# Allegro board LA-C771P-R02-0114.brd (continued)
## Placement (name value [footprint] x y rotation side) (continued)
RX6  -  [R_0402]  51.14 93.02 90 bottom
RX7  -  [R0402_0OHM]  48.93 92.08 0 bottom
RX8  -  [R_0402]  50.2 93.99 180 bottom
RX9  -  [R0805_0OHM]  73.36 98.61 270 bottom
RX10  -  [R0603_0OHM]  54.82 90.15 90 bottom
RX11  -  [R_0402]  50.83 83.57 0 bottom
RX12  -  [R0402_0OHM]  50.12 95.89 0 bottom
RX13  -  [R0402_0OHM]  50.12 96.78 0 bottom
RY1  -  [R_0402]  18.96 84.2 180 top
RY2  -  [R_0402]  13.87 94.75 90 top
RY3  -  [R_0402]  18.96 85.22 180 top
RY4  -  [R_0402]  18.96 81.03 180 top
RY5  -  [R_0402]  18.96 80.15 180 top
RY6  -  [R_0402]  18.96 82.94 180 top
RY7  -  [R_0402]  18.96 86.13 180 top
RY8  -  [R_0402]  18.96 82.05 180 top
RY9  -  [R_0402]  18.97 87.15 180 top
RY10  -  [R_0402]  15.52 93.78 0 top
RY11  -  [R_0402]  21.03 87.09 180 bottom
RY12  -  [R_0402]  18.7 86.24 90 bottom
RY13  -  [R_0402]  21.03 86.2 180 bottom
RY14  -  [R_0402]  21.2 82.01 180 bottom
RY15  -  [R_0402]  18.83 83.06 270 bottom
RY16  -  [R_0402]  21.2 82.9 180 bottom
RY17  -  [R_0402]  20.99 85.15 180 bottom
RY18  -  [R_0402]  18.7 84.46 90 bottom
RY19  -  [R_0402]  20.99 84.27 180 bottom
RY20  -  [R_0402]  21.17 80.11 180 bottom
RY21  -  [R_0402]  18.83 81.29 270 bottom
RY22  -  [R_0402]  21.17 81.01 180 bottom
SW3  -  [SW_TJG-533-V-T-R_6P]  108.35 5.6 90 top
SW4  -  [SW_TJG-533-V-T-R_6P]  180.1 5.6 90 top
SW5  -  [SW_NTC325-EA1J-A160C_3P]  4.3 9.89 270 top
T1  -  [TPC12]  94.57 75.22 180 bottom
T2  -  [TPC12]  95.85 75.45 180 bottom
T3  -  [TPC12]  116.69 83.85 0 top
T4  -  [TPC12]  122.84 78.45 180 bottom
T5  -  [TPC12]  123.63 81.42 180 bottom
T6  -  [TPC12]  122.72 82.5 315 top
T7  -  [TPC12]  124.63 88 180 bottom
T8  -  [TPC12]  101.61 78.79 45 top
T9  -  [TPC12]  93.68 80.91 180 bottom
T10  -  [TPC12]  101.68 80.07 0 top
T11  -  [TPC12]  102.93 80.68 0 top
T12  -  [TPC12]  101.84 81.44 0 top
T13  -  [TPC12]  102.27 82.68 0 top
T14  -  [TPC12]  119.28 83.83 315 top
T15  -  [TPC12]  118.73 81.77 315 top
T16  -  [TPC12]  123.81 76.2 180 bottom
T17  -  [TPC12]  122.95 77.13 180 bottom
T18  -  [TPC12]  123.58 74.92 180 bottom
T19  -  [TPC12]  123.63 73.52 180 bottom
T20  -  [TPC12]  106.2 79.74 45 top
T21  -  [TPC12]  110.05 76.67 45 top
T22  -  [TPC12]  222.82 108.92 0 top
TL1  -  [MHPC_NS681612A_16P]  26.84 70.09 270 bottom
TPL1  -  [TPC12]  39.73 64.11 180 bottom
TPL2  -  [TPC12]  37.98 65.06 180 bottom
UA1  -  [ALC233-VB2-CG_MQFN48_6X6]  26.97 27.53 180 top
UB1  -  [NPCE388NA0DX_LQFP128_14X14]  78.13 27.8 270 top
UC4  -  [VALLEYVIEW-M_FCBGA_1170P-T]  97.84 90.26 90 bottom
UC5  -  [SN74LVC1G07DCKR_SC70-5]  56.65 80.15 270 bottom
UC6  -  [SN74LVC1G07DCKR_SC70-5]  61.96 80.26 270 bottom
UC7  -  [SN74LVC1G07DCKR_SC70-5]  83.27 75.11 90 top
UC8  -  [TC7SH08FUF_SSOP5]  78.66 80.92 90 top
UC9  -  [SN74LVC1G07DCKR_SC70-5]  95.41 95 270 bottom
UC10  -  [W25Q64DWSSIG_SO8]  54.83 46.05 180 top
UL1  -  [RTL8111GS-CG_QFN32_4X4]  33.63 67.35 90 bottom
UQ1  -  [TPS22966DPUR_SON14_2X3]  189.53 24.2 90 top
UQ2  -  [TPS22966DPUR_SON14_2X3]  51.18 68.68 270 top
UQ3  -  [AO4304L_SO8]  156.71 53.14 270 top
UR1  -  [RTS5220-GRT_QFN24_4X4]  48.68 15.53 270 top
US1  -  [SY6288D20AAC_SOT23-5]  18.38 39.3 180 bottom
US2  -  [FE1P1S-BQFN24B_WQFN24_4X4]  197.75 57.57 180 top
US3  -  [SY6288D20AAC_SOT23-5]  186.98 53.6 270 top
UW1  -  [Z32H320TC-LPC-T28-233_TSSOP28]  98.54 20.3 90 top
UW2  -  [MAX9180EXTLFT_SC70-6]  99.04 15.59 90 top
UX1  -  [SY6288C20AAC_SOT23-5]  72.07 86.41 270 top
UY1  -  [AP2330W-7_SC59-3]  16.92 89.41 180 top
YC1  -  [Y_7V25000014_4P]  111.07 95.72 180 bottom
YC2  -  [Y_Q13FC135000040_2P]  90.65 92.26 270 bottom
YL1  -  [Y_X3G025000DC1H_4P]  37.65 61.4 270 bottom
YS1  -  [Y_CRG3201212_4P]  202.09 60.46 180 top

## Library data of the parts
C1 C5 C6 C9-C11 CB1 CB8 CB13 CB14 CC1 CC6-CC11 CC15 CC17 CC22 CC23 CC30 CC79 CC85 CC89 CC90 CC92 CD1 CD3 CD8-CD15 CD19 CO12 CQ3-CQ5 CQ7 CQ11-CQ13 CQ15 CQ19 CQ20 CS1-CS3 CS7 CS8 CS13 CX3-CX8 CX11 CX13 CY1-CY12 = C_0402: tolerance: .1U_0402_16V7K
C2 C12 CO13 CO14 = C_0603: tolerance: 0.1U_0603_6.3V6M
C3 C4 CB7 CB10 CC2-CC5 CC14 CC16 CC21 PC101 PC102 PC713 PC757 = C_0402: tolerance: 100P_0402_50V8J
CA1 CA3 CA5-CA7 CM1 = C_0402: tolerance: 0.1U_0402_16VK7
CA2 CA8 CA9 CA15 CA20 CA22-CA24 CC24 CC25 CC29 CC31 CC32 CC41-CC53 CC56-CC71 CC74 CC76-CC78 CC80-CC84 CC87 CC88 CC91 CC93 CD17 CD18 CL1 CL6 CO11 CQ1 CQ8 CQ9 CQ16 CR10 CX2 CX10 PC601 PC706-PC708 PC733 PC738 = C_0402: tolerance: 1U_0402_6.3V6K
CA4 CA18 CB11 CL9 CL10 CQ17 CQ18 CR1 CR3 CR5 CR11 CX1 PC602 = C_0603: tolerance: 4.7U_0603_6.3V6K
CA10 = C_0402: tolerance: 22P_0402_50V8J
CA11 CA14 CA17 CA19 CS5 CS6 PC714 PC756 = C_0402: tolerance: 470P_0402_50V7K
CA12 CA13 CA16 CA21 CA25 CC33-CC36 PC781 PC784 = C_0402: tolerance: 2.2U_0402_6.3V6M
CA28 CA29 CB2 CB5 CB6 PC100 PC103 PC104 PC210 PC705 = C_0402: tolerance: 1000P_0402_50V7K
CA30 CA32 = C_0402: tolerance: 0.1U_0402_16V4Z
CA31 CL2-CL5 CL7 CL8 CL11 CL12 CR2 CR4 CR6-CR8 CR12 PC501 PC603 PC710-PC712 PC750 = C_0402: tolerance: 0.1U_0402_16V7K
CB3 CB4 CW1-CW4 = C_0201: tolerance: 0.1U_0201_10V6K
CB12 PC744 = C_0402: tolerance: 47P_0402_50V8J
CC12 CC13 = C_0402: tolerance: 10P_0402_25V8J
CC18 CC19 = C_0402: tolerance: 15P_0402_50V8J
CC20 CC94 CC95 CD2 = C_0402: tolerance: 100P_0402_25V8K
CC26-CC28 CL13 CL16 = C_0402: tolerance: 10P_0402_50V8J
CC37-CC40 CC72 CC73 CC75 CD4-CD7 CD16 CO9 CO10 CS9 CX12 PC406 PC407 PC702-PC704 PC715 PC718 PC723 PC766 PC770 PC774 PC777 PC779 = C_0603: tolerance: 10U_0603_6.3V6M
CC54 = C_0402: tolerance: 0.47U_0402_6.3V6K
CC55 CC86 CL15 CO1-CO8 CS11 CS12 = C_0402: tolerance: 0.01U_0402_16V7K
CL14 = C_0603: tolerance: 10P_0603_50V
CLRP1 CLRP2 J1 J2 = SHORTPADS: User Part Number: PART#; tolerance: SHORT PADS
CQ2 CQ6 CQ10 CQ14 PC724 PC752 PC762 = C_0402: tolerance: 330P_0402_50V7K
CR9 = C_0402: tolerance: 5.6P 50V D NPO 0402
CS4 CS14 = C_MP6VLPS220MC4R2: tolerance: 220U_6.3V_M
CS10 PC311 PC320 PC325 = C_0603: tolerance: 4.7U_0603_6.3V6M
CX9 = C_0805: tolerance: 4.7U_0805_25V6-K
CX14 CX15 = C_0402: tolerance: 33P_0402_50V8K
D1 = YSLC05CH_SOT23-3
D2 = PSOT24C_SOT23-3: tolerance: L30ESD24VC3-2
D3 = PSOT24C_SOT23-3: tolerance: SCA00002900
D4 DA3-DA5 = L03ESDL5V0CC3-2_SOT23-3
DC1 = RB751V40_SC76-2
DL1 = BS4200N-C-LV_SMB-F2
DL2 DS2 DS3 = AZC099-04SPR7G_SOT23-6: tolerance: AZC099-04S.R7G_SOT23-6
DS1 DY1-DY3 = L05ESDL5V0NA-4_SLP2510P8-10-9
FD1-FD4 = FIDUCIAL_C40M80: tolerance: CF
H1-H5 H7 H8 H13 H14 = H_3P0: tolerance: HOLEA
H6 = H_3P1X3P6: tolerance: HOLEA
H9-H12 = H_3P8: tolerance: HOLEA
JBATT1 = SUYIN_125022HB008M200ZL_8P-T: tolerance: SUYIN_125022HB008M200ZL
JDCIN1 = ACES_50299-00501-003_5P: tolerance: ACES_88299-0510
JDIMM1 = LCN_DAN06-K4406-0102_204P: tolerance: LCN_DAN06-K4406-0102
JEDP1 = ACES_87242-3001-09_30P: tolerance: ACES_87242-3001-09
JHDD1 = SDAN_603015-022041_22P-T: tolerance: SDAN_603015-022041
JHDMI1 = LOTES_AHDM0006-P004A_19P: tolerance: LOTES_AHDM0006-P004A
JHP1 = SANTA_311108-1_7P: tolerance: SANTA_311108-1
JKB1 JKB2 = ACES_88514-3001_30P: tolerance: ACES_88514-3001
JLAN1 = SANTA_130452-S_8P: tolerance: SANTA_130452-S
JODD1 = SANTA_201304-1_13P: tolerance: SANTA_201304-1
JP1 = ACES_85205-0400_4P: tolerance: ACES_85205-0400
JPWRB1 JSB1 JTP1 = ACES_88058-060N_6P: tolerance: ACES_88058-060N
JRTC1 = LOTES_AAA-BAT-054-K01_2P: tolerance: LOTES_AAA-BAT-054-K01
JSD1 = FOX_WK21921-R93-9H_11P: tolerance: FOX_WK21921-R93-9H
JSPK1 = E-T_3806K-F02N-03R_2P: tolerance: E&T_3806K-F02N-03R
JUSB1 = SINGA_2UB4039-200011F_9P: tolerance: SINGA_2UB4039-200011F
JUSB2 = SDAN_608050-004041_4P: tolerance: SDAN_608050-004041
JWLAN1 = BELLW_80019-1021_52P: tolerance: BELLW_80019-1021
L1 L2 = TDK_MPZ2012S101AT000_2P: tolerance: MPZ2012S101AT000_2P
L3 L4 = L_FBM-11-160808_2P: tolerance: FBM-11-160808-601-T_0603
LA1 LA2 = CHENG_MBK1608121YZF_2P: tolerance: FCM1608CF-121T03 0603
LED1 LED3 LED4 = LED_19-217-T1D-DP1Q2QY-3T_2P: tolerance: 19-217-T1D-DP1Q2QY-3T_WHITE
LED2 = LED_19-213A-T1D-CP2Q2HY-3T_2P: tolerance: 19-217/S2C-FM2P1VY/3T 0603 ORANGE
LR1 = MURAT_BLM18PG300SN1D_2P: tolerance: PBY160808T-301Y-N_0603
LS1 LS2 = INPAQ_HCM1012GH900BP_4P: tolerance: PANASONIC EXC24CH900U
LS3 LS4 LX1 LY1-LY4 = INPAQ_HCM1012GH900BP_4P: tolerance: HCM1012GH900BP_4P
MIC1 = MIC_WM-64PCY_2P: tolerance: KECG2242PFL-B4
PC105 PC209 PC302 PC604 = C_0402: tolerance: 0.01U_0402_25V7K
PC200 = C_0603: tolerance: 1000P_0603_50V7
PC201 = C_0603: tolerance: 0.022U_0603_25V7K
PC202 PC214 = C_0603: tolerance: 0.047U_0603_25V7M
PC203 PC503 = C_0402: tolerance: 68P_0402_50V8J
PC204 PC212 PC303 PC316 PC402 PC720 = C_0402: tolerance: 2200P_0402_50V7K
PC205 PC206 PC218 PC220 PC305 PC306 PC314 PC315 PC403 PC404 PC721 PC722 PC739 PC741 = C_0805: tolerance: 10U_0805_25V6K
PC207 = C_0603: tolerance: 0.1U_0603_25V7M
PC208 PC217 PC221-PC223 PC301 PC319 PC401 PC725 PC740 PC751 = C_0402: tolerance: 0.1U_0402_25V6
PC211 = C_0603: tolerance: 1U_0603_25V6K
PC213 = C_0805: tolerance: 2.2U_0805_25V6K
PC215 PC216 = C_0603: tolerance: 100P_0603_50V8
PC219 PC312 PC326 = C_0603: tolerance: 680P_0603_50V7K
PC304 PC318 PC405 = C_0603: tolerance: 0.1U_0603_25V7K
PC307-PC310 PC321-PC324 PC409-PC414 PC502 PC504-PC507 PC605 PC732 PC734-PC736 PC742 PC743 PC745-PC749 PC764 PC765 PC767-PC769 PC771 PC773 PC775 PC778 PC780 PC783 = C_0603: tolerance: 22U_0603_6.3V6M
PC313 = C_0402: tolerance: 4.7U_0402_6.3V6M
PC317 PC716 PC761 = C_0402: tolerance: 6800P_0402_25V7K
PC327 = C_0402: tolerance: 1000P_0402_25V8J
PC408 PC416 = C_0402: tolerance: 1U_0402_10V6K
PC415 = C_0402: tolerance: 0.033U_0402_16V7K
PC417 PC508 PC731 PC755 = C_0402: tolerance: 680P_0402_50V7K
PC418 PC419 = C_0402: tolerance: 0.1U_0402_10V7K
PC701 = C_6P3X4P5: tolerance: 33U_25V_NC_6.3X4.5
PC709 PC763 = C_0402: tolerance: 0.01UF_0402_25V7K
PC717 = C_0402: tolerance: 10U_0402_6.3V6M
PC719 PC760 = C_0402: tolerance: 1000P_0402_50V8-J
PC726 PC759 = C_0402: tolerance: 0.1U_0402_25V6K
PC727 PC758 = C_0402: tolerance: 0.047U_0402_25V7K
PC772 PC776 = C_0603: tolerance: 4.7U_0603_10V6K
PC782 PC785-PC787 = C_D2: tolerance: 330U_D2_2V_Y
PD1 PD100 = RB715F_SOT323-3: tolerance: S SCH DIO BAS40CW SOT-323
PF100 PF101 = F_1206: tolerance: 7A_24VDC_429007.WRML
PH100 = R_0402: tolerance: 100K_0402_1%_TSM0B104F4251RZ
PH701 PH702 = R_0402: tolerance: 10K_0402_1%_B25/50 3370K
PH703 PH704 = R_0402: tolerance: 470K_0402_5%_B25/50 4700K
PJ1-PJ4 = JUMP_43X118: tolerance: JUMP
PJ5 PJ6 = JUMP_43X79: tolerance: JUMP
PJ301 PJ302 PJ401 PJ402 = JUMP_43X118
PJ403 = JUMP_43X39
PJ501 PJ502 PJ601 PJ602 = JUMP_43X79
PL100-PL103 PL301 PL303 PL401 PL701 = TAI-T_HCB2012KF-121T50_2P: tolerance: HCB2012KF-121T50_0805
PL200 = TAIYO_NRS4018T1R0NDGJ_2P: tolerance: 1UH_NRS4018T1R0NDGJ_3.2A_30%
PL201 = CYNTE_PCMB063T-4R7MS_2P: tolerance: 4.7UH_PCMB063T-4R7MS_5.5A_20%
PL302 PL304 = CYNTE_PCMC063T-1R5MN_2P: tolerance: 1.5UH_PCMC063T-1R5MN_9A_20%
PL402 = L_7X7X3_M_2P: tolerance: 1UH_11A_20%_7X7X3_M
PL403 = L_4X4X2_F_2P: tolerance: 1UH_2.8A_30%_4X4X2_F
PL702 PL703 = CYNTE_PDME064T-R36MS1R405_4P: tolerance: 0.36UH_PDME064T-R36MS_24A_20%
PQ200 = 2N7002KW_SOT323-3
PQ201 = MDU1512RH_POWERDFN56-8-5
PQ202 = AON7506_DFN33-8-5
PQ203 = AO4466L_SO8: tolerance: AO4406L_SO8
PQ204 PQ205 = SIS412DN-T1-GE3_POWERPAK8-5: tolerance: AON7408L_DFN8-5
PQ401 = AON7408L_DFN8-5
PQ402 = AON7406L_DFN8-5
PQ701 PQ702 = AON7934_DFN3X3A8-10: tolerance: AON7934_DFN3X3A-8-10
PR102 PR104 RC71-RC73 = R_0402: tolerance: 100_0402_1%
PR105 PR107 RA16 = R_0402: tolerance: 200K_0402_1%
PR109 RA10 RA22 RA23 RA31 RB12 RB18 RB20 RB21 RB27 RB31 RB32 RC14 RC15 RC17 RC21 RC22 RC27-RC29 RC32-RC36 RC43 RC58 RC59 RC61 RC63 RC81 RL4 RM18-RM20 RQ8 RQ9 RR8 RS10 RS14 RW8 RX3 RY2 = R_0402: tolerance: 10K_0402_5%
PR110 = R_0402: tolerance: 16.5K_0402_1%
PR111 PR409 PR605 = R_0402: tolerance: 10K_0402_1%
PR112 = R_0402: tolerance: 30K_0402_1%
PR113 PR225 PR228 RC1 RC2 RX8 = R_0402: tolerance: 100K_0402_1%
PR115 PR116 = R_0603: tolerance: 1K_0603_5%
PR122 PR218 PR219 PR224 PR307 PR410 PR411 PR501 PR717 PR718 PR722 R1 R15 RA8 RA9 RA12 RA21 RA24 RA26 RA28 RB7 RB22 RB24 RB26 RC10 RC13 RC23 RC48 RC70 RC74 RC75 RC80 RD5 RD6 RL5 RL7 RM4-RM6 RR5-RR7 RS6-RS9 RX1 RX7 RX12 RX13 = R0402_0OHM: tolerance: 0_0402_5%
PR123 R2 R12 RB1 RB3 RB6 RB11 RB13 RB16 RB17 RB23 RB25 RB29 RB30 RC8 RC12 RC54 RC62 RC78 RC79 RC83 RC84 RM2 RM3 RM11 RM12 RM14-RM17 RM21 RO5 RS1-RS5 RS16-RS20 RW1 RW3 RW4 RW6 RW9 RX6 = R_0402: tolerance: 0_0402_5%
PR200 PR308 = R_0402: tolerance: 1M_0402_1%
PR201 = R_0402: tolerance: 3M_0402_5%
PR202 PR221 = R_1206_4P-D: tolerance: 0.01_1206_1%
PR209 PR211 PR212 RC30 = R_0402: tolerance: 4.02K_0402_1%
PR210 = R_0603: tolerance: 4.7_0603_1%
PR213 PR226 PR227 = R_0402: tolerance: 10_0402_1%
PR214 = R_1206: tolerance: 10_1206_5%
PR215 = R_0402: tolerance: 422K_0402_1%
PR216 = R_0402: tolerance: 66.5K_0402_1%
PR217 PR220 PR708 PR728 RB2 RS15 = R_0603: tolerance: 0_0603_5%
PR222 = R_0402: tolerance: 316K_0402_1%
PR223 PR305 PR311 PR403 PR713 PR731 = R_1206: tolerance: 4.7_1206_5%
PR229 = R_0402: tolerance: 120K_0402_1%
PR301 = R_0402: tolerance: 499K_0402_1%
PR302 PR309 RA30 RL2 = R_0402: tolerance: 1K_0402_5%
PR303 = R_0402: tolerance: 150K_0402_1%
PR304 PR310 PR401 PR709 PR730 = R_0603: tolerance: 2.2_0603_5%
PR306 RA6 RA7 RA27 RC9 RC26 RW5 RW7 = R_0402: tolerance: 2.2K_0402_5%
PR312 = R_0402: tolerance: 560K_0402_5%
PR313 = R_0402: tolerance: 105K_0402_1%
PR314 PR406 PR502 PR602 R3 R16 RA14 RA15 RC37 RM13 RQ1 RQ5 RS12 RS13 RX2 RX4 RX5 RY10 = R_0402: tolerance: 100K_0402_5%
PR402 = R_0402: tolerance: 27K_0402_1%
PR404 PR405 = R_0603: tolerance: 5.1_0603_5%
PR407 = R_0402: tolerance: 8.06K_0402_1%
PR408 = R_0402: tolerance: 470K_0402_1%
PR503 RC24 = R_0402: tolerance: 1M_0402_5%
PR504 = R_0603: tolerance: 4.7_0603_5%
PR505 = R_0402: tolerance: 15K_0402_1%
PR506 RC47 RC49 = R_0402: tolerance: 20K_0402_1%
PR601 = R_0402: tolerance: 100_0402_5%
PR603 = R_0402: tolerance: 12.7K_0402_1%
PR604 RB5 RB10 RQ4 = R_0402: tolerance: 47K_0402_5%
PR701 PR724 PR736 = R_0402: tolerance: 499_0402_1%
PR702 PR741 = R_0402: tolerance: 137K_0402_1%
PR703 = R_0402: tolerance: 2.05K_0402_1%
PR704 PR705 PR733 PR737 = R_0402: tolerance: 2K_0402_1%
PR706 = R_0402: tolerance: 316_0402_1%
PR707 = R_0402: tolerance: 21K_0402_1%
PR710 PR734 = R_0402: tolerance: 2.61K_0402_1%
PR711 PR739 = R_0402: tolerance: 11K_0402_1%
PR712 PR729 = R_0402: tolerance: 1.91K_0402_1%
PR714 PR735 = R_0603: tolerance: 3.65K_0603_1%
PR715 PR727 = R_0402: tolerance: 27.4K_0402_1%
PR716 PR723 = R_0402: tolerance: 3.83K_0402_1%
PR719 = R_0402: tolerance: 1_0402_5%
PR720 RC40 = R_0402: tolerance: 20_0402_1%
PR721 RC41 = R_0402: tolerance: 16.9_0402_1%
PR725 PR726 RC39 = R_0402: tolerance: 73.2_0402_1%
PR732 = R_0402: tolerance: 64.9K_0402_1%
PR738 = R_0402: tolerance: 280_0402_1%
PR740 = R_0402: tolerance: 1.78K_0402_1%
PU1 = BQ24780RUYR_WQFN28_4X4
PU301 = SYX196BQNC_QFN10_3X3
PU302 = SYX196CQNC_QFN10_3X3: tolerance: SYX196C1QNC_QFN10_3X3
PU303 = RT8207PGQW_WQFN20_3X3
PU501 = SY8003DFC_DFN8_2X2: tolerance: SY8003ADFC_DFN8_2X2
PU601 = APL5930KAI-TRG_SO8: tolerance: AP7175SP-13 SO-8EP
PU602 = ISL95833HRTZ-T_TQFN32_4X4
Q2-Q5 QB1 QX1 = 2N7002K_SOT23-3
QC1-QC5 QY2 QY3 = MESS138W-G_SOT323-3: tolerance: BSS138W-7-F_SOT323-3
QM1 = AO5804EL_SC89-6: tolerance: DMN2400UV-7 2N SOT-563-6
QX2 = PMV65XP_SOT23-3: tolerance: DMG2301U-7 1P SOT23-3
QY1 = DMN66D0LDW-7_SOT363-6
R6 = R_0402: tolerance: 300_0402_5%
R7 = R_0402: tolerance: 620_0402_5%
R13 R14 = R_0402: tolerance: 330_0402_5%
RA1-RA5 RB4 RC76 RC77 RL1 RX10 = R0603_0OHM: tolerance: 0_0603_5%
RA11 RA13 RC53 RR4 RW2 = R_0402: tolerance: 33_0402_5%
RA17 RA18 = R_0603: tolerance: TAI-TECH FCM1608CF-121T03 0603
RA19 RA20 = R_0402: tolerance: 47_0402_5%
RA25 RA29 RB8 RB9 RB14 RB15 RC25 = R_0402: tolerance: 4.7K_0402_5%
RA32 = R_0402: tolerance: 0_0402_1%
RC3 = R_0402: tolerance: 23.2_0402_1%
RC4 = R_0402: tolerance: 29.4_0402_1%
RC5 = R_0402: tolerance: 162_0402_1%
RC6 RC7 RD1-RD4 = R_0402: tolerance: 4.7K_0402_1%
RC11 RC16 RC18 = R_0402: tolerance: 402_0402_1%
RC19 RC44 RC65 = R_0402: tolerance: 49.9_0402_1%
RC20 = R_0402: tolerance: 69.8_0402_1%
RC31 = R_0402: tolerance: 47.5_0402_1%
RC38 RC46 = R_0402: tolerance: 51_0402_5%
RC42 = R_0402: tolerance: 10M_0402_5%
RC45 = R_0402: tolerance: 200_0402_5%
RC50-RC52 = R_0402: tolerance: 3.3K_0402_5%
RC55 = R_0402: tolerance: 1.24K_0402_1%
RC56 RC57 = R_0402: tolerance: 1K_0402_1%
RC60 RC64 = R_0402: tolerance: 45.3_0402_1%
RC66 RC67 = R_0402: tolerance: 22_0402_5%
RC68 RC82 = R_0402: tolerance: 8.2K_0402_5%
RC69 = R_0402: tolerance: BLM15AX601SN1D
RL3 = R_0402: tolerance: 15K_0402_5%
RL6 = R_0402: tolerance: 2.49K_0402_1%
RL8 = R_0805: tolerance: 75_0805_5%
RM1 RO1 RO2 RO4 RX9 = R0805_0OHM: tolerance: 0_0805_5%
RPB1 RPY1 = RP_0804_8P4R: tolerance: 2.2K_0804_8P4R_5%
RPC1 RPC9 = RP_0804_8P4R: tolerance: 4.7K_0804_8P4R_5%
RPC2 = RP_0804_8P4R: tolerance: 100K_0804_8P4R_5%
RPC3 RPC5 = RP_0804_8P4R: tolerance: 10K_0804_8P4R_5%
RPC4 = RP_0804_8P4R: tolerance: 33_0804_8P4R_5%
RPC6 = RP_0804_8P4R: tolerance: 51_0804_8P4R_5%
RPC7 RPC8 = RP_0804_8P4R: tolerance: 22_0804_8P4R_5%
RQ2 = R_0402: tolerance: 120K_0402_5%
RQ3 = R_0402: tolerance: 82K_0402_5%
RQ6 = R_0603: tolerance: 22_0603_5%
RQ7 = R_0603: tolerance: 470_0603_5%
RR1 = R_0402: tolerance: 6.2K_0402_1%
RR2 RR3 = R0402_0OHM: tolerance: 0_0402_5%; signal model: R_0402_22_0402_5%
RS11 = R_0402: tolerance: 2.7K_0402_1%
RX11 = R_0402: tolerance: 150K_0402_5%
RY1 RY3-RY9 = R_0402: tolerance: 619_0402_1%
RY11 RY13 RY14 RY16 RY17 RY19 RY20 RY22 = R_0402: tolerance: 8.2_0402_1%
RY12 RY15 RY18 RY21 = R_0402: tolerance: 150_0402_5%
SW3 SW4 = SW_TJG-533-V-T-R_6P: tolerance: SMT1-05_4P
SW5 = SW_NTC325-EA1J-A160C_3P: tolerance: NTC325-EA1J-A160C_3P
T1-T22 = TPC12: tolerance: PAD
TL1 = MHPC_NS681612A_16P: tolerance: 300UH_NS681612A
TPL1 TPL2 = TPC12: tolerance: PAD~D
UA1 = ALC233-VB2-CG_MQFN48_6X6
UB1 = NPCE388NA0DX_LQFP128_14X14
UC4 = VALLEYVIEW-M_FCBGA_1170P-T: tolerance: FH8065301546401_FCBGA131170
UC5-UC7 UC9 = SN74LVC1G07DCKR_SC70-5: tolerance: NL17SZ07DFT2G_SC70-5
UC8 = TC7SH08FUF_SSOP5
UC10 = W25Q64DWSSIG_SO8: tolerance: W25Q64FWSSIG_SO8
UL1 = RTL8111GS-CG_QFN32_4X4: tolerance: RTL8107E-CG QFN 32P E-LAN CTRL
UQ1 UQ2 = TPS22966DPUR_SON14_2X3: tolerance: AOZ1331 TDFN2X3
UQ3 = AO4304L_SO8: tolerance: ME4856_SO8
UR1 = RTS5220-GRT_QFN24_4X4
US1 US3 = SY6288D20AAC_SOT23-5
US2 = FE1P1S-BQFN24B_WQFN24_4X4: tolerance: FE1.1S-BQFN24B_WQFN24_4X4
UW1 = Z32H320TC-LPC-T28-233_TSSOP28
UW2 = MAX9180EXTLFT_SC70-6: tolerance: G2129TL1U_SC70-6
UX1 = SY6288C20AAC_SOT23-5
UY1 = AP2330W-7_SC59-3
YC1 = Y_7V25000014_4P: tolerance: 25MHZ_10PF_7V25000014
YC2 = Y_Q13FC135000040_2P: tolerance: 32.768KHZ_12.5PF_Q13FC135000040
YL1 = Y_X3G025000DC1H_4P: tolerance: 25MHZ_10PF _X1E000311000900
YS1 = Y_CRG3201212_4P: tolerance: 12MHZ_18PF_7V12000001

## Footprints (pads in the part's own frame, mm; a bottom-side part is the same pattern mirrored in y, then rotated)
2N7002K_SOT23-3
  oval 1.016x1.524 smd: 1(0,0) 2(0.965,2.083) 3(-0.965,2.083)
2N7002KW_SOT323-3
  oval 0.813x0.914 smd: 1(0,0) 2(0.65,1.6) 3(-0.65,1.6)
ACES_50299-00501-003_5P
  round 1.803 hole 1.803 unplated: (-0.2,5.2) (8.2,5.2)
  oval 0.889x2.388 smd: 1(0,0) 2(2,0) 3(4,0) 4(6,0) 5(8,0)
ACES_85205-0400_4P
  oval 0.813x1.626 smd: 1(0,0) 2(1.25,0) 3(2.5,0) 4(3.75,0)
  rect 2.032x3.048 smd: 5(-2.55,-2.9) 6(6.3,-2.9)
ACES_87242-3001-09_30P
  oval 0.61x1.499 smd: 1(0,0) 2(0,-6.1) 3(1,0) 4(1,-6.1) 5(2,0) 6(2,-6.1) 7(3,0) 8(3,-6.1) 9(4,0) 10(4,-6.1) 11(5,0) 12(5,-6.1) 13(6,0) 14(6,-6.1) 15(7,0) 16(7,-6.1) 17(8,0) 18(8,-6.1) 19(9,0) 20(9,-6.1) 21(10,0) 22(10,-6.1) 23(11,0) 24(11,-6.1) 25(12,0) 26(12,-6.1) 27(13,0) 28(13,-6.1) 29(14,0) 30(14,-6.1)
  rect 1.499x2.007 smd: 31(-2,-4.6) 32(16,-4.6)
ACES_88058-060N_6P
  oval 0.61x1.092 smd: 1(0,0) 2(-1,0) 3(-2,0) 4(-3,0) 5(-4,0) 6(-5,0)
  rect 2.388x2.997 smd: 7(2.9,-2.05) 8(-7.9,-2.05)
ACES_88514-3001_30P
  oval 0.61x1.295 smd: 1(0,0) 2(1,0) 3(2,0) 4(3,0) 5(4,0) 6(5,0) 7(6,0) 8(7,0) 9(8,0) 10(9,0) 11(10,0) 12(11,0) 13(12,0) 14(13,0) 15(14,0) 16(15,0) 17(16,0) 18(17,0) 19(18,0) 20(19,0) 21(20,0) 22(21,0) 23(22,0) 24(23,0) 25(24,0) 26(25,0) 27(26,0) 28(27,0) 29(28,0) 30(29,0)
  rect 2.159x2.21 smd: 31(-2.825,-3.05) 32(31.825,-3.05)
ALC233-VB2-CG_MQFN48_6X6
  oval 0.203x0.889 smd: 1(0,0) 2(0.4,0) 3(0.8,0) 4(1.2,0) 5(1.6,0) 6(2,0) 7(2.4,0) 8(2.8,0) 9(3.2,0) 10(3.6,0) 11(4,0) 12(4.4,0) 25(4.4,6.1) 26(4,6.1) 27(3.6,6.1) 28(3.2,6.1) 29(2.8,6.1) 30(2.4,6.1) 31(2,6.1) 32(1.6,6.1) 33(1.2,6.1) 34(0.8,6.1) 35(0.4,6.1) 36(0,6.1)
  oval 0.889x0.203 smd: 13(5.25,0.85) 14(5.25,1.25) 15(5.25,1.65) 16(5.25,2.05) 17(5.25,2.45) 18(5.25,2.85) 19(5.25,3.25) 20(5.25,3.65) 21(5.25,4.05) 22(5.25,4.45) 23(5.25,4.85) 24(5.25,5.25) 37(-0.85,5.25) 38(-0.85,4.85) 39(-0.85,4.45) 40(-0.85,4.05) 41(-0.85,3.65) 42(-0.85,3.25) 43(-0.85,2.85) 44(-0.85,2.45) 45(-0.85,2.05) 46(-0.85,1.65) 47(-0.85,1.25) 48(-0.85,0.85)
  rect 4.394x4.394 smd: 49(2.2,3.05)
AO4304L_SO8
  oval 0.635x1.854 smd: 1(0,0) 2(1.27,0) 3(2.54,0) 4(3.81,0) 5(3.81,5.165) 6(2.54,5.165) 7(1.27,5.165) 8(0,5.165)
AO4466L_SO8
  oval 0.635x1.854 smd: 1(0,0) 2(1.27,0) 3(2.54,0) 4(3.81,0) 5(3.81,5.165) 6(2.54,5.165) 7(1.27,5.165) 8(0,5.165)
AO5804EL_SC89-6
  oval 0.305x0.457 smd: 1(0,0) 2(0.5,0) 3(1,0) 4(1,1.25) 5(0.5,1.25) 6(0,1.25)
AON7406L_DFN8-5
  oval 0.406x0.991 smd: 1(0,0) 2(0.66,0) 3(1.32,0) 4(1.98,0)
  custom 0.559x0.559 smd: 5(0.99,2.247)
AON7408L_DFN8-5
  oval 0.406x0.991 smd: 1(0,0) 2(0.66,0) 3(1.32,0) 4(1.98,0)
  custom 0.559x0.559 smd: 5(0.99,2.247)
AON7506_DFN33-8-5
  oval 0.406x0.991 smd: 1(0,0) 2(0.66,0) 3(1.32,0) 4(1.98,0)
  custom 0.559x0.559 smd: 5(0.99,2.247)
AON7934_DFN3X3A8-10
  oval 0.457x0.508 smd: 1(0,0) 2(0.65,0) 3(1.3,0) 4(1.95,0) 5(1.95,2.76) 6(1.3,2.76) 7(0.65,2.76) 8(0,2.76)
  rect 2.54x1.041 smd: 9(0.975,1.813)
  rect 2.54x0.559 smd: 10(0.975,0.708)
AP2330W-7_SC59-3
  oval 0.787x0.991 smd: 1(0,0) 2(-0.95,-2.4) 3(0.95,-2.4)
APL5930KAI-TRG_SO8
  oval 0.635x1.854 smd: 1(0,0) 2(1.27,0) 3(2.54,0) 4(3.81,0) 5(3.81,5.165) 6(2.54,5.165) 7(1.27,5.165) 8(0,5.165)
  rect 2.87x2.489 smd: 9(1.905,2.582)
AZC099-04SPR7G_SOT23-6
  oval 0.559x1.092 smd: 1(0,0) 2(0.95,0) 3(1.9,0) 4(1.9,2.5) 5(0.95,2.5) 6(0,2.5)
BELLW_80019-1021_52P
  round 1.6 hole 1.6 unplated: (-25.55,-1.8) (1.95,-1.8)
  oval 0.61x2.007 smd: 1(0,0) 3(-0.8,0) 5(-1.6,0) 7(-2.4,0) 9(-3.2,0) 11(-4,0) 13(-4.8,0) 15(-5.6,0) 17(-9.6,0) 19(-10.4,0) 21(-11.2,0) 23(-12,0) 25(-12.8,0) 27(-13.6,0) 29(-14.4,0) 31(-15.2,0) 33(-16,0) 35(-16.8,0) 37(-17.6,0) 39(-18.4,0) 41(-19.2,0) 43(-20,0) 45(-20.8,0) 47(-21.6,0) 49(-22.4,0) 51(-23.2,0)
  oval 0.61x1.524 hole 0.457x0.914: 2(-0.4,-2.4) 4(-1.2,-2.4) 6(-2,-2.4) 8(-2.8,-2.4) 10(-3.6,-2.4) 12(-4.4,-2.4) 14(-5.2,-2.4) 16(-6,-2.4) 18(-10,-2.4) 20(-10.8,-2.4) 22(-11.6,-2.4) 24(-12.4,-2.4) 26(-13.2,-2.4) 28(-14,-2.4) 30(-14.8,-2.4) 32(-15.6,-2.4) 34(-16.4,-2.4) 36(-17.2,-2.4) 38(-18,-2.4) 40(-18.8,-2.4) 42(-19.6,-2.4) 44(-20.4,-2.4) 46(-21.2,-2.4) 48(-22,-2.4) 50(-22.8,-2.4) 52(-23.6,-2.4)
  oval 1.549x2.769 hole 0.787x2.007: 53(5.075,-8.4) 54(-28.675,-8.4)
BQ24780RUYR_WQFN28_4X4
  oval 0.889x0.203 smd: 1(0,0) 2(0,-0.4) 3(0,-0.8) 4(0,-1.2) 5(0,-1.6) 6(0,-2) 7(0,-2.4) 15(4.1,-2.4) 16(4.1,-2) 17(4.1,-1.6) 18(4.1,-1.2) 19(4.1,-0.8) 20(4.1,-0.4) 21(4.1,0)
  oval 0.203x0.889 smd: 8(0.85,-3.25) 9(1.25,-3.25) 10(1.65,-3.25) 11(2.05,-3.25) 12(2.45,-3.25) 13(2.85,-3.25) 14(3.25,-3.25) 22(3.25,0.85) 23(2.85,0.85) 24(2.45,0.85) 25(2.05,0.85) 26(1.65,0.85) 27(1.25,0.85) 28(0.85,0.85)
  rect 2.591x2.591 smd: 29(2.05,-1.2)
BS4200N-C-LV_SMB-F2
  rect 2.159x2.743 smd: 1(0,0) 2(4.42,0)
C_6P3X4P5
  oval 3.505x1.6 smd: 1(0,0) 2(5.6,0)
C_0201
  rect 0.381x0.356 smd: 1(0,0) 2(0.584,0)
C_0402
  rect 0.508x0.559 smd: 1(0,0) 2(0.914,0)
C_0603
  rect 0.635x0.889 smd: 1(0,0) 2(1.397,0)
C_0805
  rect 0.813x1.397 smd: 1(0,0) 2(1.702,0)
C_D2
  rect 2.388x2.794 smd: 1(0,0) 2(6.4,0)
C_MP6VLPS220MC4R2
  oval 3.505x1.6 smd: 1(0,0) 2(-5.6,0)
CHENG_MBK1608121YZF_2P
  rect 0.991x0.787 smd: 1(0,0) 2(1.6,0)
CYNTE_PCMB063T-4R7MS_2P
  rect 2.362x3.505 smd: 1(0,0) 2(6.05,0)
CYNTE_PCMC063T-1R5MN_2P
  rect 2.159x3.505 smd: 1(0,0) 2(5.85,0)
CYNTE_PDME064T-R36MS1R405_4P
  custom 0.686x0.686 smd: 1(0,0) 4(8.509,0)
  rect 2.362x0.508 smd: 2(1.448,0) 3(7.061,0)
DMN66D0LDW-7_SOT363-6
  oval 0.432x0.61 smd: 1(0,0) 2(0.65,0) 3(1.3,0) 4(1.3,1.9) 5(0.65,1.9) 6(0,1.9)
E-T_3806K-F02N-03R_2P
  oval 0.787x1.905 smd: 1(0,0) 2(1.25,0)
  rect 1.295x3.353 smd: 3(-2.85,-4.875) 4(4.1,-4.875)
F_1206
  rect 1.295x1.803 smd: 1(0,0) 2(2.5,0)
FE1P1S-BQFN24B_WQFN24_4X4
  oval 0.889x0.254 smd: 1(0,0) 2(0,-0.5) 3(0,-1) 4(0,-1.5) 5(0,-2) 6(0,-2.5) 13(4.1,-2.5) 14(4.1,-2) 15(4.1,-1.5) 16(4.1,-1) 17(4.1,-0.5) 18(4.1,0)
  oval 0.254x0.889 smd: 7(0.8,-3.3) 8(1.3,-3.3) 9(1.8,-3.3) 10(2.3,-3.3) 11(2.8,-3.3) 12(3.3,-3.3) 19(3.3,0.8) 20(2.8,0.8) 21(2.3,0.8) 22(1.8,0.8) 23(1.3,0.8) 24(0.8,0.8)
  rect 2.794x2.794 smd: 25(2.05,-1.25)
FIDUCIAL_C40M80
  round 1.016 smd: 1(0,0)
FOX_WK21921-R93-9H_11P
  round 1.702 hole 1.702 unplated: (-5.08,-8.05) (20.22,-8.05)
  oval 0.991x2.489 smd: 1(0,0) 2(2.5,0) 3(5,0) 4(7.5,0) 5(10,0) 6(12.5,0) 7(14.92,0) 8(16.62,0) 9(-2.5,0) 10(-4.2,0) 11(18.42,0)
  rect 2.057x2.489 smd: 12(22.795,-16.4) 13(-7.655,-16.4)
H_3P0
  round 3.505 hole 2.997: 1(0,0)
H_3P1X3P6
  oval 3.607x4.115 hole 3.099x3.607: 1(0,0)
H_3P8
  round 4.318 hole 3.81: 1(0,0)
INPAQ_HCM1012GH900BP_4P
  rect 0.711x0.305 smd: 1(0,0) 2(1.25,0) 3(1.25,-0.5) 4(0,-0.5)
ISL95833HRTZ-T_TQFN32_4X4
  oval 0.203x0.914 smd: 1(0,0) 2(0.4,0) 3(0.8,0) 4(1.2,0) 5(1.6,0) 6(2,0) 7(2.4,0) 8(2.8,0) 17(2.8,4.077) 18(2.4,4.077) 19(2,4.077) 20(1.6,4.077) 21(1.2,4.077) 22(0.8,4.077) 23(0.4,4.077) 24(0,4.077)
  oval 0.914x0.203 smd: 9(3.438,0.639) 10(3.438,1.039) 11(3.438,1.438) 12(3.438,1.838) 13(3.438,2.239) 14(3.438,2.639) 15(3.438,3.039) 16(3.438,3.438) 25(-0.639,3.438) 26(-0.639,3.039) 27(-0.639,2.639) 28(-0.639,2.239) 29(-0.639,1.838) 30(-0.639,1.438) 31(-0.639,1.039) 32(-0.639,0.639)
  rect 2.692x2.692 smd: 33(1.4,2.039)
JUMP_43X39
  custom 0.191x0.191 smd: 1(0,0) 2(0.914,0)
JUMP_43X79
  custom 0.188x0.188 smd: 1(0,0) 2(1.1,0)
JUMP_43X118
  custom 0.187x0.187 smd: 1(0,0) 2(1.1,0)
L03ESDL5V0CC3-2_SOT23-3
  oval 1.016x1.524 smd: 1(0,0) 2(0.965,2.083) 3(-0.965,2.083)
L05ESDL5V0NA-4_SLP2510P8-10-9
  rect 0.203x0.686 smd: 1(0,0) 2(-0.5,0) 4(-1.5,0) 5(-2,0) 6(-2,-0.875) 7(-1.5,-0.875) 8(-0.5,-0.875) 9(0,-0.875)
  rect 0.406x1.549 smd: 3(-1,-0.437)
L_4X4X2_F_2P
  rect 1.194x3.708 smd: 1(0,0) 2(2.8,0)
L_7X7X3_M_2P
  rect 2.362x3.505 smd: 1(0,0) 2(6.05,0)
L_FBM-11-160808_2P
  oval 0.864x1.219 smd: 1(0,0) 2(1.422,0)
LCN_DAN06-K4406-0102_204P
  round 1.6 hole 1.6 unplated: (-1.75,4.1)
  round 1.092 hole 1.092 unplated: (65.05,4.1)
  oval 0.356x2.007 smd: 1(0,0) 2(0.3,8.2) 3(0.6,0) 4(0.9,8.2) 5(1.2,0) 6(1.5,8.2) 7(1.8,0) 8(2.1,8.2) 9(2.4,0) 10(2.7,8.2) 11(3,0) 12(3.3,8.2) 13(3.6,0) 14(3.9,8.2) 15(4.2,0) 16(4.5,8.2) 17(4.8,0) 18(5.1,8.2) 19(5.4,0) 20(5.7,8.2) 21(6,0) 22(6.3,8.2) 23(6.6,0) 24(6.9,8.2) 25(7.2,0) 26(7.5,8.2) 27(7.8,0) 28(8.1,8.2) 29(8.4,0) 30(8.7,8.2) 31(9,0) 32(9.3,8.2) 33(9.6,0) 34(9.9,8.2) 35(10.2,0) 36(10.5,8.2) 37(10.8,0) 38(11.1,8.2) 39(11.4,0) 40(11.7,8.2) 41(12,0) 42(12.3,8.2) 43(12.6,0) 44(12.9,8.2) 45(13.2,0) 46(13.5,8.2) 47(13.8,0) 48(14.1,8.2) 49(14.4,0) 50(14.7,8.2) 51(15,0) 52(15.3,8.2) 53(15.6,0) 54(15.9,8.2) 55(16.2,0) 56(16.5,8.2) 57(16.8,0) 58(17.1,8.2) 59(17.4,0) 60(17.7,8.2) 61(18,0) 62(18.3,8.2) 63(18.6,0) 64(18.9,8.2) 65(19.2,0) 66(19.5,8.2) 67(19.8,0) 68(20.1,8.2) 69(20.4,0) 70(20.7,8.2) 71(21,0) 72(21.3,8.2) 73(24,0) 74(24.3,8.2) 75(24.6,0) 76(24.9,8.2) 77(25.2,0) 78(25.5,8.2) 79(25.8,0) 80(26.1,8.2) 81(26.4,0) 82(26.7,8.2) 83(27,0) 84(27.3,8.2) 85(27.6,0) 86(27.9,8.2) 87(28.2,0) 88(28.5,8.2) 89(28.8,0) 90(29.1,8.2) 91(29.4,0) 92(29.7,8.2) 93(30,0) 94(30.3,8.2) 95(30.6,0) 96(30.9,8.2) 97(31.2,0) 98(31.5,8.2) 99(31.8,0) 100(32.1,8.2) 101(32.4,0) 102(32.7,8.2) 103(33,0) 104(33.3,8.2) 105(33.6,0) 106(33.9,8.2) 107(34.2,0) 108(34.5,8.2) 109(34.8,0) 110(35.1,8.2) 111(35.4,0) 112(35.7,8.2) 113(36,0) 114(36.3,8.2) 115(36.6,0) 116(36.9,8.2) 117(37.2,0) 118(37.5,8.2) 119(37.8,0) 120(38.1,8.2) 121(38.4,0) 122(38.7,8.2) 123(39,0) 124(39.3,8.2) 125(39.6,0) 126(39.9,8.2) 127(40.2,0) 128(40.5,8.2) 129(40.8,0) 130(41.1,8.2) 131(41.4,0) 132(41.7,8.2) 133(42,0) 134(42.3,8.2) 135(42.6,0) 136(42.9,8.2) 137(43.2,0) 138(43.5,8.2) 139(43.8,0) 140(44.1,8.2) 141(44.4,0) 142(44.7,8.2) 143(45,0) 144(45.3,8.2) 145(45.6,0) 146(45.9,8.2) 147(46.2,0) 148(46.5,8.2) 149(46.8,0) 150(47.1,8.2) 151(47.4,0) 152(47.7,8.2) 153(48,0) 154(48.3,8.2) 155(48.6,0) 156(48.9,8.2) 157(49.2,0) 158(49.5,8.2) 159(49.8,0) 160(50.1,8.2) 161(50.4,0) 162(50.7,8.2) 163(51,0) 164(51.3,8.2) 165(51.6,0) 166(51.9,8.2) 167(52.2,0) 168(52.5,8.2) 169(52.8,0) 170(53.1,8.2) 171(53.4,0) 172(53.7,8.2) 173(54,0) 174(54.3,8.2) 175(54.6,0) 176(54.9,8.2) 177(55.2,0) 178(55.5,8.2) 179(55.8,0) 180(56.1,8.2) 181(56.4,0) 182(56.7,8.2) 183(57,0) 184(57.3,8.2) 185(57.6,0) 186(57.9,8.2) 187(58.2,0) 188(58.5,8.2) 189(58.8,0) 190(59.1,8.2) 191(59.4,0) 192(59.7,8.2) 193(60,0) 194(60.3,8.2) 195(60.6,0) 196(60.9,8.2) 197(61.2,0) 198(61.5,8.2) 199(61.8,0) 200(62.1,8.2) 201(62.4,0) 202(62.7,8.2) 203(63,0) 204(63.3,8.2)
  rect 3.505x4.597 smd: 205(-1.15,16.1) 206(64.45,16.1)
LED_19-213A-T1D-CP2Q2HY-3T_2P
  rect 0.787x0.787 smd: 1(0,0) 2(1.5,0)
LED_19-217-T1D-DP1Q2QY-3T_2P
  rect 0.787x0.787 smd: 1(0,0) 2(1.5,0)
LOTES_AAA-BAT-054-K01_2P
  round 0.787 hole 0.787 unplated: (-14.5,-8)
  round 1.194 hole 1.194 unplated: (-14.5,8)
  rect 2.007x3.988 smd: 1(0,0) 2(-30.1,0)
LOTES_AHDM0006-P004A_19P
  round 0.813 hole 0.559: 1(0,0) 2(0.5,1.55) 3(1,0) 4(1.5,1.55) 5(2,0) 6(2.5,1.55) 7(3,0) 8(3.5,1.55) 9(4,0) 10(4.5,1.55) 11(5,0) 12(5.5,1.55) 13(6,0) 14(6.5,1.55) 15(7,0) 16(7.5,1.55) 17(8,0) 18(8.5,1.55) 19(9,0)
  oval 1.499x2.21 hole 0.889x1.6: 20(-4.65,-1.45) 21(-4.65,-6.5) 22(13.65,-1.45) 23(13.65,-6.5)
MAX9180EXTLFT_SC70-6
  oval 0.356x1.143 smd: 1(0,0) 2(0.65,0) 3(1.3,0) 4(1.3,1.9) 5(0.65,1.9) 6(0,1.9)
MDU1512RH_POWERDFN56-8-5
  oval 0.61x1.27 smd: 1(0,0) 2(1.27,0) 3(2.54,0) 4(3.81,0)
  custom 1.105x1.105 smd: 5(1.905,3.715)
MESS138W-G_SOT323-3
  oval 0.711x0.889 smd: 1(0,0) 2(-0.65,-1.9) 3(0.65,-1.9)
MHPC_NS681612A_16P
  oval 0.635x1.905 smd: 1(0,0) 2(1.27,0) 3(2.54,0) 4(3.81,0) 5(5.08,0) 6(6.35,0) 7(7.62,0) 8(8.89,0) 9(8.89,8.765) 10(7.62,8.765) 11(6.35,8.765) 12(5.08,8.765) 13(3.81,8.765) 14(2.54,8.765) 15(1.27,8.765) 16(0,8.765)
MIC_WM-64PCY_2P
  round 1.626 hole 0.61: 1(0,0) 2(-1.9,0)
MURAT_BLM18PG300SN1D_2P
  rect 0.66x1.041 smd: 1(0,0) 2(1.2,0)
NPCE388NA0DX_LQFP128_14X14
  oval 1.753x0.203 smd: 1(0,0) 2(0,-0.4) 3(0,-0.8) 4(0,-1.2) 5(0,-1.6) 6(0,-2) 7(0,-2.4) 8(0,-2.8) 9(0,-3.2) 10(0,-3.6) 11(0,-4) 12(0,-4.4) 13(0,-4.8) 14(0,-5.2) 15(0,-5.6) 16(0,-6) 17(0,-6.4) 18(0,-6.8) 19(0,-7.2) 20(0,-7.6) 21(0,-8) 22(0,-8.4) 23(0,-8.8) 24(0,-9.2) 25(0,-9.6) 26(0,-10) 27(0,-10.4) 28(0,-10.8) 29(0,-11.2) 30(0,-11.6) 31(0,-12) 32(0,-12.4) 65(15.654,-12.4) 66(15.654,-12) 67(15.654,-11.6) 68(15.654,-11.2) 69(15.654,-10.8) 70(15.654,-10.4) 71(15.654,-10) 72(15.654,-9.6) 73(15.654,-9.2) 74(15.654,-8.8) 75(15.654,-8.4) 76(15.654,-8) 77(15.654,-7.6) 78(15.654,-7.2) 79(15.654,-6.8) 80(15.654,-6.4) 81(15.654,-6) 82(15.654,-5.6) 83(15.654,-5.2) 84(15.654,-4.8) 85(15.654,-4.4) 86(15.654,-4) 87(15.654,-3.6) 88(15.654,-3.2) 89(15.654,-2.8) 90(15.654,-2.4) 91(15.654,-2) 92(15.654,-1.6) 93(15.654,-1.2) 94(15.654,-0.8) 95(15.654,-0.4) 96(15.654,0)
  oval 0.203x1.753 smd: 33(1.627,-14.027) 34(2.027,-14.027) 35(2.427,-14.027) 36(2.827,-14.027) 37(3.227,-14.027) 38(3.627,-14.027) 39(4.027,-14.027) 40(4.427,-14.027) 41(4.827,-14.027) 42(5.227,-14.027) 43(5.627,-14.027) 44(6.027,-14.027) 45(6.427,-14.027) 46(6.827,-14.027) 47(7.227,-14.027) 48(7.627,-14.027) 49(8.027,-14.027) 50(8.427,-14.027) 51(8.827,-14.027) 52(9.227,-14.027) 53(9.627,-14.027) 54(10.027,-14.027) 55(10.427,-14.027) 56(10.827,-14.027) 57(11.227,-14.027) 58(11.627,-14.027) 59(12.027,-14.027) 60(12.427,-14.027) 61(12.827,-14.027) 62(13.227,-14.027) 63(13.627,-14.027) 64(14.027,-14.027) 97(14.027,1.627) 98(13.627,1.627) 99(13.227,1.627) 100(12.827,1.627) 101(12.427,1.627) 102(12.027,1.627) 103(11.627,1.627) 104(11.227,1.627) 105(10.827,1.627) 106(10.427,1.627) 107(10.027,1.627) 108(9.627,1.627) 109(9.227,1.627) 110(8.827,1.627) 111(8.427,1.627) 112(8.027,1.627) 113(7.627,1.627) 114(7.227,1.627) 115(6.827,1.627) 116(6.427,1.627) 117(6.027,1.627) 118(5.627,1.627) 119(5.227,1.627) 120(4.827,1.627) 121(4.427,1.627) 122(4.027,1.627) 123(3.627,1.627) 124(3.227,1.627) 125(2.827,1.627) 126(2.427,1.627) 127(2.027,1.627) 128(1.627,1.627)
PMV65XP_SOT23-3
  oval 1.016x1.524 smd: 1(0,0) 2(0.965,2.083) 3(-0.965,2.083)
PSOT24C_SOT23-3
  oval 1.016x1.524 smd: 1(0,0) 2(0.965,2.083) 3(-0.965,2.083)
R0402_0OHM
  rect 0.508x0.559 smd: 1(0,0) 2(0.914,0)
R0603_0OHM
  rect 0.635x0.889 smd: 1(0,0) 2(1.397,0)
R0805_0OHM
  rect 0.813x1.397 smd: 1(0,0) 2(1.702,0)
R_0402
  rect 0.508x0.559 smd: 1(0,0) 2(0.914,0)
R_0603
  rect 0.635x0.889 smd: 1(0,0) 2(1.397,0)
R_0805
  rect 0.813x1.397 smd: 1(0,0) 2(1.702,0)
R_1206
  rect 1.016x1.651 smd: 1(0,0) 2(2.667,0)
R_1206_4P-D
  custom 0.445x0.445 smd: 1(0,0) 4(5.004,0)
  custom 0.114x0.114 smd: 2(1.194,0) 3(3.81,0)
RB715F_SOT323-3
  oval 0.813x0.914 smd: 1(0,0) 2(0.65,1.6) 3(-0.65,1.6)
RB751V40_SC76-2
  rect 0.61x0.61 smd: 1(0,0) 2(2.2,0)
RP_0804_8P4R
  oval 0.66x0.254 smd: 1(0,0) 2(0,-0.5) 3(0,-1) 4(0,-1.5) 5(1.15,-1.5) 6(1.15,-1) 7(1.15,-0.5) 8(1.15,0)
RT8207PGQW_WQFN20_3X3
  oval 0.203x0.889 smd: 1(0,0) 2(0.4,0) 3(0.8,0) 4(1.2,0) 5(1.6,0) 11(1.6,3.1) 12(1.2,3.1) 13(0.8,3.1) 14(0.4,3.1) 15(0,3.1)
  oval 0.889x0.203 smd: 6(2.35,0.75) 7(2.35,1.15) 8(2.35,1.55) 9(2.35,1.95) 10(2.35,2.35) 16(-0.75,2.35) 17(-0.75,1.95) 18(-0.75,1.55) 19(-0.75,1.15) 20(-0.75,0.75)
  rect 1.702x1.702 smd: 21(0.8,1.55)
RTL8111GS-CG_QFN32_4X4
  oval 0.203x0.914 smd: 1(0,0) 2(0.4,0) 3(0.8,0) 4(1.2,0) 5(1.6,0) 6(2,0) 7(2.4,0) 8(2.8,0) 17(2.8,4.077) 18(2.4,4.077) 19(2,4.077) 20(1.6,4.077) 21(1.2,4.077) 22(0.8,4.077) 23(0.4,4.077) 24(0,4.077)
  oval 0.914x0.203 smd: 9(3.438,0.639) 10(3.438,1.039) 11(3.438,1.438) 12(3.438,1.838) 13(3.438,2.239) 14(3.438,2.639) 15(3.438,3.039) 16(3.438,3.438) 25(-0.639,3.438) 26(-0.639,3.039) 27(-0.639,2.639) 28(-0.639,2.239) 29(-0.639,1.838) 30(-0.639,1.438) 31(-0.639,1.039) 32(-0.639,0.639)
  rect 2.692x2.692 smd: 33(1.4,2.039)
RTS5220-GRT_QFN24_4X4
  oval 0.889x0.254 smd: 1(0,0) 2(0,-0.5) 3(0,-1) 4(0,-1.5) 5(0,-2) 6(0,-2.5) 13(4.1,-2.5) 14(4.1,-2) 15(4.1,-1.5) 16(4.1,-1) 17(4.1,-0.5) 18(4.1,0)
  oval 0.254x0.889 smd: 7(0.8,-3.3) 8(1.3,-3.3) 9(1.8,-3.3) 10(2.3,-3.3) 11(2.8,-3.3) 12(3.3,-3.3) 19(3.3,0.8) 20(2.8,0.8) 21(2.3,0.8) 22(1.8,0.8) 23(1.3,0.8) 24(0.8,0.8)
  rect 2.261x2.261 smd: 25(2.05,-1.25)
SANTA_130452-S_8P
  round 1.295 hole 0.889: 1(0,0) 2(-1.02,-1.1) 3(-2.04,0) 4(-3.06,-1.1) 5(-4.08,0) 6(-5.1,-1.1) 7(-6.12,0) 8(-7.14,-1.1)
  oval 1.753x3.15 hole 0.991x2.388: 9(-11.56,-7.5) 10(4.42,-7.5)
SANTA_201304-1_13P
  round 1.194 hole 1.194 unplated: (-19.18,-1.56) (0.42,-1.56)
  round 1.016 hole 0.711: 1(0,0) 2(-1.27,0) 3(-2.54,0) 4(-3.81,0) 5(-5.08,0) 6(-6.35,0) 7(-7.62,0)
  round 0.914 hole 0.61: 8(-13.83,1) 9(-14.83,0) 10(-15.83,1) 11(-16.83,0) 12(-17.83,1) 13(-18.83,0)
  oval 1.499x3.15 hole 0.711x2.362: 14(2.22,-0.29) 15(-20.98,-0.29)
SANTA_311108-1_7P
  round 1.194 hole 1.194 unplated: (-5.2,7.6) (1.3,7.6)
  round 1.499 hole 1.092: 1(0,0) 2(0.9,2) 3(-4.55,0) 4(-5.8,3.1) 5(-6.55,6.1) 6(1.9,0) 7(-6.55,9.1)
SDAN_603015-022041_22P-T
  round 1.194 hole 1.194 unplated: (-34.875,-0.7) (3.125,-0.7)
  round 1.016 hole 0.711: 1(0,0) 2(-1.27,0) 3(-2.54,0) 4(-3.81,0) 5(-5.08,0) 6(-6.35,0) 7(-7.62,0) 8(-13.97,0) 9(-15.24,0) 10(-16.51,0) 11(-17.78,0) 12(-19.05,0) 13(-20.32,0) 14(-21.59,0) 15(-22.86,0) 16(-24.13,0) 17(-25.4,0) 18(-26.67,0) 19(-27.94,0) 20(-29.21,0) 21(-30.48,0) 22(-31.75,0)
  oval 1.473x3.15 hole 0.711x2.388: 23(-37.69,-0.3) 24(5.94,-0.3)
SDAN_608050-004041_4P
  round 1.499 hole 0.889: 1(0,0) 2(-2.5,0) 3(-4.5,0) 4(-7,0)
  oval 1.295x2.21 hole 0.711x1.803: 5(-9.9,0.3) 8(2.9,0.3)
  oval 1.295x1.803 hole 0.711x1.397: 6(-11.2,-8.25) 7(4.2,-8.25)
SHORTPADS
  custom 0.19x0.19 smd: 1(-0.483,0) 2(0.483,0)
SINGA_2UB4039-200011F_9P
  round 1.295 hole 0.711: 1(0,0) 2(-2.5,0) 3(-4.5,0) 4(-7,0) 5(-7.5,-1.5) 6(-5.5,-1.5) 7(-3.5,-1.5) 8(-1.5,-1.5) 9(0.5,-1.5)
  oval 1.194x2.311 hole 0.61x1.702: 10(2.9,0.3) 11(-9.9,0.3)
  oval 1.295x2.007 hole 0.711x1.397: 12(-11.2,-8.95) 13(4.2,-8.95)
SIS412DN-T1-GE3_POWERPAK8-5
  oval 0.406x0.991 smd: 1(0,0) 2(0.66,0) 3(1.32,0) 4(1.98,0)
  custom 0.559x0.559 smd: 5(0.99,2.247)
SN74LVC1G07DCKR_SC70-5
  oval 0.381x0.864 smd: 1(0,0) 2(0.65,0) 3(1.3,0) 4(1.3,1.74) 5(0,1.74)
SUYIN_125022HB008M200ZL_8P-T
  oval 0.787x1.295 smd: 1(0,0) 2(-1.25,0) 3(-2.5,0) 4(-3.75,0) 5(-5,0) 6(-6.25,0) 7(-7.5,0) 8(-8.75,0)
  oval 1.041x1.651 hole 0.66x1.245: 9(-10.5,-2.85) 10(-10.5,-6.325) 11(1.75,-2.85) 12(1.75,-6.325)
SW_NTC325-EA1J-A160C_3P
  round 0.889 hole 0.889 unplated: (-0.9,-0.9) (3.35,-0.9)
  custom 0.191x0.191 smd: 1(0,0) 3(2.45,0)
  oval 0.61x1.803 smd: 2(1.225,0)
  custom 0.222x0.222 hole 0.889x0.406: 4(3.025,-2) 5(-0.575,-2)
SW_TJG-533-V-T-R_6P
  rect 0.61x0.991 smd: 1(0,0) 2(0,-4.4) 3(-3.7,0) 4(-3.7,-4.4)
  rect 0.457x1.397 smd: 5(0.675,-2.2) 6(-4.375,-2.2)
SY6288C20AAC_SOT23-5
  oval 0.559x0.787 smd: 1(0,0) 2(0.95,0) 3(1.9,0) 4(1.9,2.4) 5(0,2.4)
SY6288D20AAC_SOT23-5
  oval 0.559x0.787 smd: 1(0,0) 2(0.95,0) 3(1.9,0) 4(1.9,2.4) 5(0,2.4)
SY8003DFC_DFN8_2X2
  oval 0.254x0.787 smd: 1(0,0) 2(0.5,0) 3(1,0) 4(1.5,0) 5(1.5,2.2) 6(1,2.2) 7(0.5,2.2) 8(0,2.2)
  rect 1.549x0.838 smd: 9(0.75,1.1)
SYX196BQNC_QFN10_3X3
  oval 0.254x0.61 smd: 1(0,0) 2(0.45,0) 3(0.9,0) 4(1.35,0) 5(1.8,0) 6(2.25,0)
  rect 1.118x0.229 smd: 7(2.215,-0.662)
  rect 0.864x2.007 smd: 8(2.09,-2)
  custom 0.47x0.47 smd: 9(1.077,-1.775)
  rect 0.787x1.143 smd: 10(0.113,-1.6)
SYX196CQNC_QFN10_3X3
  oval 0.254x0.61 smd: 1(0,0) 2(0.45,0) 3(0.9,0) 4(1.35,0) 5(1.8,0) 6(2.25,0)
  rect 1.118x0.229 smd: 7(2.215,-0.662)
  rect 0.864x2.007 smd: 8(2.09,-2)
  custom 0.47x0.47 smd: 9(1.077,-1.775)
  rect 0.787x1.143 smd: 10(0.113,-1.6)
TAI-T_HCB2012KF-121T50_2P
  rect 0.991x0.991 smd: 1(0,0) 2(2,0)
TAIYO_NRS4018T1R0NDGJ_2P
  rect 1.194x3.708 smd: 1(0,0) 2(2.8,0)
TC7SH08FUF_SSOP5
  oval 0.457x0.711 smd: 1(0,0) 2(0.65,0) 3(1.3,0) 4(1.3,1.875) 5(0,1.875)
TDK_MPZ2012S101AT000_2P
  rect 0.991x1.753 smd: 1(0,0) 2(1.5,0)
TPC12
  round 0.305 smd: 1(0,0)
TPS22966DPUR_SON14_2X3
  oval 0.203x0.762 smd: 1(0,0) 2(0.4,0) 3(0.8,0) 4(1.2,0) 5(1.6,0) 6(2,0) 7(2.4,0) 8(2.4,2.05) 9(2,2.05) 10(1.6,2.05) 11(1.2,2.05) 12(0.8,2.05) 13(0.4,2.05) 14(0,2.05)
  rect 2.489x0.889 smd: 15(1.2,1.025)
VALLEYVIEW-M_FCBGA_1170P-T
  round 0.521 smd: A3(-0.863,0) A52(-25.197,0) B2(-0.431,0.431) B53(-25.628,0.431) BH1(0,23.197) BH53(-25.628,23.197) BJ2(-0.431,23.628) BJ52(-25.197,23.628) C1(0,0.863)
  round 0.406 smd: A5(-1.644,0) A6(-2.368,0) A49(-23.806,0) A51(-24.587,0) B52(-25.039,0.589) BE1(0,21.806) BE53(-25.628,21.806) BG1(0,22.587) BG53(-25.628,22.587) BH2(-0.589,23.039) BH52(-25.039,23.039) BJ3(-1.041,23.628) BJ5(-1.822,23.628) BJ49(-23.806,23.628) BJ51(-24.587,23.628) C53(-25.628,1.041) E1(0,1.644) E53(-25.628,1.822) F1(0,2.368)
  round 0.356 smd: A7(-3.066,0) A9(-3.978,0) A47(-22.435,0) A48(-23.108,0) B4(-1.182,0.576) B5(-1.776,0.592) B6(-2.369,0.593) B8(-3.556,0.59) B46(-22.072,0.59) B48(-23.259,0.593) B49(-23.852,0.592) B50(-24.446,0.576) BC1(0,20.435) BC2(-0.568,20.666) BC52(-25.06,20.666) BC53(-25.628,20.435) BD1(0,21.108) BD2(-0.593,21.259) BD52(-25.035,21.259) BD53(-25.628,21.108) BE2(-0.592,21.852) BE52(-25.037,21.852) BF2(-0.576,22.446) BF52(-25.052,22.446) BG3(-1.17,22.458) BG51(-24.458,22.458) BH4(-1.182,23.052) BH5(-1.776,23.037) BH6(-2.369,23.035) BH8(-3.556,23.038) BH46(-22.072,23.038) BH48(-23.259,23.035) BH49(-23.852,23.037) BH50(-24.446,23.052) BJ6(-2.52,23.628) BJ7(-3.194,23.628) BJ47(-22.435,23.628) BJ48(-23.108,23.628) C3(-1.17,1.17) C51(-24.458,1.17) D2(-0.576,1.182) D52(-25.052,1.182) E2(-0.592,1.776) E52(-25.037,1.776) F2(-0.593,2.369) F52(-25.035,2.369) F53(-25.628,2.52) G1(0,3.135) G2(-0.568,2.962) G52(-25.06,2.962) G53(-25.628,3.194) J1(0,3.998)
  oval 0.254x0.343 smd: A11(-5.04,0) A13(-6.011,0) A15(-6.983,0) A17(-7.955,0) A19(-8.927,0) A21(-9.899,0) A23(-10.87,0) A25(-11.842,0) A27(-12.814,0) A29(-13.786,0) A31(-14.758,0) A33(-15.729,0) A35(-16.701,0) A37(-17.673,0) A39(-18.645,0) A41(-19.617,0) A43(-20.588,0) A45(-21.56,0) BJ9(-4.068,23.628) BJ11(-5.04,23.628) BJ13(-6.011,23.628) BJ15(-6.983,23.628) BJ17(-7.955,23.628) BJ19(-8.927,23.628) BJ21(-9.899,23.628) BJ23(-10.87,23.628) BJ25(-11.842,23.628) BJ27(-12.814,23.628) BJ29(-13.786,23.628) BJ31(-14.758,23.628) BJ33(-15.729,23.628) BJ35(-16.701,23.628) BJ37(-17.673,23.628) BJ39(-18.645,23.628) BJ41(-19.617,23.628) BJ43(-20.588,23.628) BJ45(-21.56,23.628)
  oval 0.343x0.254 smd: AA1(0,9.87) AA53(-25.628,9.87) AC1(0,10.842) AC53(-25.628,10.842) AE1(0,11.814) AE53(-25.628,11.814) AG1(0,12.786) AG53(-25.628,12.786) AJ1(0,13.758) AJ53(-25.628,13.758) AL1(0,14.729) AL53(-25.628,14.729) AN1(0,15.701) AN53(-25.628,15.701) AR1(0,16.673) AR53(-25.628,16.673) AU1(0,17.645) AU53(-25.628,17.645) AW1(0,18.617) AW53(-25.628,18.617) BA1(0,19.588) BA53(-25.628,19.588) J53(-25.628,4.04) L1(0,5.011) L53(-25.628,5.011) N1(0,5.983) N53(-25.628,5.983) R1(0,6.955) R53(-25.628,6.955) U1(0,7.927) U53(-25.628,7.927) W1(0,8.899) W53(-25.628,8.899)
  round 0.279 smd: AA3(-0.743,9.87) AA51(-24.885,9.87) AB2(-0.385,10.356) AB3(-1.084,10.356) AB51(-24.544,10.356) AB52(-25.243,10.356) AC3(-0.743,10.842) AC51(-24.885,10.842) AD2(-0.385,11.328) AD3(-1.099,11.334) AD51(-24.529,11.334) AD52(-25.243,11.328) AE3(-0.743,11.814) AE4(-1.448,11.814) AE50(-24.18,11.814) AE51(-24.885,11.814) AF2(-0.385,12.3) AF3(-1.099,12.294) AF51(-24.529,12.294) AF52(-25.243,12.3) AG3(-0.743,12.786) AG51(-24.885,12.786) AH2(-0.385,13.272) AH3(-1.084,13.272) AH51(-24.544,13.272) AH52(-25.243,13.272) AJ3(-0.743,13.758) AJ51(-24.885,13.758) AK2(-0.385,14.244) AK3(-1.084,14.244) AK51(-24.544,14.244) AK52(-25.243,14.244) AL3(-0.743,14.729) AL51(-24.885,14.729) AM2(-0.385,15.215) AM3(-1.084,15.215) AM51(-24.544,15.215) AM52(-25.243,15.215) AN3(-0.743,15.701) AN51(-24.885,15.701) AP2(-0.385,16.187) AP3(-1.084,16.187) AP51(-24.544,16.187) AP52(-25.243,16.187) AR3(-0.743,16.673) AR51(-24.885,16.673) AT2(-0.385,17.159) AT3(-1.084,17.159) AT51(-24.544,17.159) AT52(-25.243,17.159) AU3(-0.743,17.645) AU51(-24.885,17.645) AV2(-0.385,18.131) AV3(-1.084,18.131) AV51(-24.544,18.131) AV52(-25.243,18.131) AW3(-0.743,18.617) AW51(-24.885,18.617) AY2(-0.385,19.103) AY3(-1.084,19.103) AY51(-24.544,19.103) AY52(-25.243,19.103) B10(-4.554,0.385) B12(-5.526,0.385) B14(-6.497,0.385) B16(-7.469,0.385) B18(-8.441,0.385) B20(-9.413,0.385) B22(-10.385,0.385) B24(-11.356,0.385) B26(-12.328,0.385) B28(-13.3,0.385) B30(-14.272,0.385) B32(-15.244,0.385) B34(-16.215,0.385) B36(-17.187,0.385) B38(-18.159,0.385) B40(-19.131,0.385) B42(-20.103,0.385) B44(-21.074,0.385) BA3(-0.743,19.588) BA51(-24.885,19.588) BB3(-0.885,20.165) BB51(-24.743,20.165) BF27(-12.814,22.18) BG9(-4.116,22.842) BG11(-5.04,22.885) BG12(-5.526,22.544) BG13(-6.011,22.885) BG14(-6.497,22.544) BG15(-6.983,22.885) BG16(-7.469,22.544) BG17(-7.955,22.885) BG18(-8.441,22.544) BG19(-8.927,22.885) BG20(-9.413,22.544) BG21(-9.899,22.885) BG22(-10.385,22.544) BG23(-10.87,22.885) BG24(-11.356,22.544) BG25(-11.842,22.885) BG26(-12.334,22.529) BG27(-12.814,22.885) BG28(-13.294,22.529) BG29(-13.786,22.885) BG30(-14.272,22.544) BG31(-14.758,22.885) BG32(-15.244,22.544) BG33(-15.729,22.885) BG34(-16.215,22.544) BG35(-16.701,22.885) BG36(-17.187,22.544) BG37(-17.673,22.885) BG38(-18.159,22.544) BG39(-18.645,22.885) BG40(-19.131,22.544) BG41(-19.617,22.885) BG42(-20.103,22.544) BG43(-20.588,22.885) BG45(-21.512,22.842) BH10(-4.554,23.243) BH12(-5.526,23.243) BH14(-6.497,23.243) BH16(-7.469,23.243) BH18(-8.441,23.243) BH20(-9.413,23.243) BH22(-10.385,23.243) BH24(-11.356,23.243) BH26(-12.328,23.243) BH28(-13.3,23.243) BH30(-14.272,23.243) BH32(-15.244,23.243) BH34(-16.215,23.243) BH36(-17.187,23.243) BH38(-18.159,23.243) BH40(-19.131,23.243) BH42(-20.103,23.243) BH44(-21.074,23.243) C9(-4.116,0.786) C11(-5.04,0.743) C12(-5.526,1.084) C13(-6.011,0.743) C14(-6.497,1.084) C15(-6.983,0.743) C16(-7.469,1.084) C17(-7.955,0.743) C18(-8.441,1.084) C19(-8.927,0.743) C20(-9.413,1.084) C21(-9.899,0.743) C22(-10.385,1.084) C23(-10.87,0.743) C24(-11.356,1.084) C25(-11.842,0.743) C26(-12.334,1.099) C27(-12.814,0.743) C28(-13.294,1.099) C29(-13.786,0.743) C30(-14.272,1.084) C31(-14.758,0.743) C32(-15.244,1.084) C33(-15.729,0.743) C34(-16.215,1.084) C35(-16.701,0.743) C36(-17.187,1.084) C37(-17.673,0.743) C38(-18.159,1.084) C39(-18.645,0.743) C40(-19.131,1.084) C41(-19.617,0.743) C42(-20.103,1.084) C43(-20.588,0.743) C45(-21.512,0.786) D27(-12.814,1.448) H3(-0.885,3.463) H51(-24.743,3.463) J3(-0.743,4.04) J51(-24.885,4.04) K2(-0.385,4.526) K3(-1.084,4.526) K51(-24.544,4.526) K52(-25.243,4.526) L3(-0.743,5.011) L51(-24.885,5.011) M2(-0.385,5.497) M3(-1.084,5.497) M51(-24.544,5.497) M52(-25.243,5.497) N3(-0.743,5.983) N51(-24.885,5.983) P2(-0.385,6.469) P3(-1.084,6.469) P51(-24.544,6.469) P52(-25.243,6.469) R3(-0.743,6.955) R51(-24.885,6.955) T2(-0.385,7.441) T3(-1.084,7.441) T51(-24.544,7.441) T52(-25.243,7.441) U3(-0.743,7.927) U51(-24.885,7.927) V2(-0.385,8.413) V3(-1.084,8.413) V51(-24.544,8.413) V52(-25.243,8.413) W3(-0.743,8.899) W51(-24.885,8.899) Y2(-0.385,9.385) Y3(-1.084,9.385) Y51(-24.544,9.385) Y52(-25.243,9.385)
  round 0.33 smd: AA16(-7.507,9.853) AA18(-8.265,9.853) AA19(-9.023,9.853) AA21(-9.781,9.853) AA22(-10.539,9.853) AA24(-11.298,9.853) AA25(-12.056,9.853) AA27(-12.814,9.853) AA29(-13.572,9.853) AA30(-14.33,9.853) AA32(-15.089,9.853) AA33(-15.847,9.853) AA35(-16.605,9.853) AA36(-17.363,9.853) AA38(-18.121,9.853) AC16(-7.507,10.638) AC18(-8.265,10.638) AC19(-9.023,10.638) AC21(-9.781,10.638) AC22(-10.539,10.638) AC24(-11.298,10.638) AC25(-12.056,10.638) AC27(-12.814,10.638) AC29(-13.572,10.638) AC30(-14.33,10.638) AC32(-15.089,10.638) AC33(-15.847,10.638) AC35(-16.605,10.638) AC36(-17.363,10.638) AC38(-18.121,10.638) AD16(-7.507,11.422) AD18(-8.265,11.422) AD19(-9.023,11.422) AD21(-9.781,11.422) AD22(-10.539,11.422) AD24(-11.298,11.422) AD25(-12.056,11.422) AD27(-12.814,11.422) AD29(-13.572,11.422) AD30(-14.33,11.422) AD32(-15.089,11.422) AD33(-15.847,11.422) AD35(-16.605,11.422) AD36(-17.363,11.422) AD38(-18.121,11.422) AF16(-7.507,12.206) AF18(-8.265,12.206) AF19(-9.023,12.206) AF21(-9.781,12.206) AF22(-10.539,12.206) AF24(-11.298,12.206) AF25(-12.056,12.206) AF27(-12.814,12.206) AF29(-13.572,12.206) AF30(-14.33,12.206) AF32(-15.089,12.206) AF33(-15.847,12.206) AF35(-16.605,12.206) AF36(-17.363,12.206) AF38(-18.121,12.206) AG16(-7.507,12.991) AG18(-8.265,12.991) AG19(-9.023,12.991) AG21(-9.781,12.991) AG22(-10.539,12.991) AG24(-11.298,12.991) AG25(-12.056,12.991) AG27(-12.814,12.991) AG29(-13.572,12.991) AG30(-14.33,12.991) AG32(-15.089,12.991) AG33(-15.847,12.991) AG35(-16.605,12.991) AG36(-17.363,12.991) AG38(-18.121,12.991) AJ16(-7.507,13.775) AJ18(-8.265,13.775) AJ19(-9.023,13.775) AJ21(-9.781,13.775) AJ22(-10.539,13.775) AJ24(-11.298,13.775) AJ25(-12.056,13.775) AJ27(-12.814,13.775) AJ29(-13.572,13.775) AJ30(-14.33,13.775) AJ32(-15.089,13.775) AJ33(-15.847,13.775) AJ35(-16.605,13.775) AJ36(-17.363,13.775) AJ38(-18.121,13.775) AK16(-7.507,14.559) AK18(-8.265,14.559) AK19(-9.023,14.559) AK21(-9.781,14.559) AK22(-10.539,14.559) AK24(-11.298,14.559) AK25(-12.056,14.559) AK27(-12.814,14.559) AK29(-13.572,14.559) AK30(-14.33,14.559) AK32(-15.089,14.559) AK33(-15.847,14.559) AK35(-16.605,14.559) AK36(-17.363,14.559) AK38(-18.121,14.559) AM16(-7.507,15.344) AM18(-8.265,15.344) AM19(-9.023,15.344) AM21(-9.781,15.344) AM22(-10.539,15.344) AM24(-11.298,15.344) AM25(-12.056,15.344) AM27(-12.814,15.344) AM29(-13.572,15.344) AM30(-14.33,15.344) AM32(-15.089,15.344) AM33(-15.847,15.344) AM35(-16.605,15.344) AM36(-17.363,15.344) AM38(-18.121,15.344) AN16(-7.507,16.128) AN18(-8.265,16.128) AN19(-9.023,16.128) AN21(-9.781,16.128) AN22(-10.539,16.128) AN24(-11.298,16.128) AN25(-12.056,16.128) AN27(-12.814,16.128) AN29(-13.572,16.128) AN30(-14.33,16.128) AN32(-15.089,16.128) AN33(-15.847,16.128) AN35(-16.605,16.128) AN36(-17.363,16.128) AN38(-18.121,16.128) U16(-7.507,7.5) U18(-8.265,7.5) U19(-9.023,7.5) U21(-9.781,7.5) U22(-10.539,7.5) U24(-11.298,7.5) U25(-12.056,7.5) U27(-12.814,7.5) U29(-13.572,7.5) U30(-14.33,7.5) U32(-15.089,7.5) U33(-15.847,7.5) U35(-16.605,7.5) U36(-17.363,7.5) U38(-18.121,7.5) V16(-7.507,8.284) V18(-8.265,8.284) V19(-9.023,8.284) V21(-9.781,8.284) V22(-10.539,8.284) V24(-11.298,8.284) V25(-12.056,8.284) V27(-12.814,8.284) V29(-13.572,8.284) V30(-14.33,8.284) V32(-15.089,8.284) V33(-15.847,8.284) V35(-16.605,8.284) V36(-17.363,8.284) V38(-18.121,8.284) Y16(-7.507,9.069) Y18(-8.265,9.069) Y19(-9.023,9.069) Y21(-9.781,9.069) Y22(-10.539,9.069) Y24(-11.298,9.069) Y25(-12.056,9.069) Y27(-12.814,9.069) Y29(-13.572,9.069) Y30(-14.33,9.069) Y32(-15.089,9.069) Y33(-15.847,9.069) Y35(-16.605,9.069) Y36(-17.363,9.069) Y38(-18.121,9.069)
  round 0.305 smd: AB4(-1.677,10.366) AB6(-2.351,10.366) AB7(-3.062,10.366) AB9(-3.773,10.366) AB10(-4.484,10.366) AB12(-5.196,10.366) AB13(-5.907,10.366) AB14(-6.618,10.366) AB40(-19.01,10.366) AB41(-19.721,10.366) AB42(-20.433,10.366) AB44(-21.144,10.366) AB45(-21.855,10.366) AB47(-22.566,10.366) AB48(-23.277,10.366) AB50(-23.951,10.366) AD4(-1.819,11.351) AD6(-2.41,11.289) AD7(-3.062,11.339) AD9(-3.773,11.339) AD10(-4.484,11.339) AD12(-5.196,11.339) AD13(-5.907,11.339) AD14(-6.618,11.339) AD40(-19.01,11.339) AD41(-19.721,11.339) AD42(-20.433,11.339) AD44(-21.144,11.339) AD45(-21.855,11.339) AD47(-22.566,11.339) AD48(-23.218,11.289) AD50(-23.809,11.351) AE6(-2.706,11.814) AE8(-3.418,11.814) AE9(-4.129,11.814) AE11(-4.84,11.814) AE12(-5.551,11.814) AE14(-6.262,11.814) AE40(-19.366,11.814) AE42(-20.077,11.814) AE43(-20.788,11.814) AE45(-21.499,11.814) AE46(-22.211,11.814) AE48(-22.922,11.814) AF4(-1.819,12.277) AF6(-2.41,12.339) AF7(-3.062,12.289) AF9(-3.773,12.289) AF10(-4.484,12.289) AF12(-5.196,12.289) AF13(-5.907,12.289) AF14(-6.618,12.289) AF40(-19.01,12.289) AF41(-19.721,12.289) AF42(-20.433,12.289) AF44(-21.144,12.289) AF45(-21.855,12.289) AF47(-22.566,12.289) AF48(-23.218,12.339) AF50(-23.809,12.277) AH4(-1.677,13.262) AH6(-2.351,13.262) AH7(-3.062,13.262) AH9(-3.773,13.262) AH10(-4.484,13.262) AH12(-5.196,13.262) AH13(-5.907,13.262) AH14(-6.618,13.262) AH40(-19.01,13.262) AH41(-19.721,13.262) AH42(-20.433,13.262) AH44(-21.144,13.262) AH45(-21.855,13.262) AH47(-22.566,13.262) AH48(-23.277,13.262) AH50(-23.951,13.262) AK4(-1.677,14.253) AK6(-2.351,14.253) AK7(-3.062,14.253) AK9(-3.773,14.253) AK10(-4.484,14.253) AK12(-5.196,14.253) AK13(-5.907,14.253) AK14(-6.618,14.253) AK40(-19.01,14.253) AK41(-19.721,14.253) AK42(-20.433,14.253) AK44(-21.144,14.253) AK45(-21.855,14.253) AK47(-22.566,14.253) AK48(-23.277,14.253) AK50(-23.951,14.253) AM4(-1.677,15.2) AM6(-2.351,15.226) AM7(-3.062,15.226) AM9(-3.773,15.226) AM10(-4.484,15.226) AM12(-5.196,15.226) AM13(-5.907,15.226) AM14(-6.618,15.226) AM40(-19.01,15.226) AM41(-19.721,15.226) AM42(-20.433,15.226) AM44(-21.144,15.226) AM45(-21.855,15.226) AM47(-22.566,15.226) AM48(-23.277,15.226) AM50(-23.951,15.2) AN5(-1.995,15.701) AN6(-2.706,15.701) AN8(-3.418,15.701) AN9(-4.129,15.701) AN11(-4.84,15.701) AN12(-5.551,15.701) AN14(-6.262,15.701) AN40(-19.366,15.701) AN42(-20.077,15.701) AN43(-20.788,15.701) AN45(-21.499,15.701) AN46(-22.211,15.701) AN48(-22.922,15.701) AN49(-23.633,15.701) AP4(-1.677,16.202) AP6(-2.351,16.176) AP7(-3.062,16.176) AP9(-3.773,16.176) AP10(-4.484,16.176) AP12(-5.196,16.176) AP13(-5.907,16.176) AP14(-6.618,16.176) AP40(-19.01,16.176) AP41(-19.721,16.176) AP42(-20.433,16.176) AP44(-21.144,16.176) AP45(-21.855,16.176) AP47(-22.566,16.176) AP48(-23.277,16.176) AP50(-23.951,16.202) AT4(-1.677,17.15) AT6(-2.351,17.15) AT7(-3.062,17.15) AT9(-3.773,17.15) AT10(-4.484,17.15) AT12(-5.196,17.15) AT13(-5.907,17.15) AT14(-6.509,17.15) AT16(-7.479,17.01) AT18(-8.452,17.01) AT19(-8.927,17.366) AT20(-9.402,17.01) AT22(-10.375,17.01) AT24(-11.366,17.01) AT26(-12.339,17.01) AT27(-12.814,17.366) AT28(-13.289,17.01) AT30(-14.262,17.01) AT32(-15.253,17.01) AT34(-16.226,17.01) AT35(-16.701,17.366) AT36(-17.176,17.01) AT38(-18.15,17.01) AT40(-19.119,17.15) AT41(-19.721,17.15) AT42(-20.433,17.15) AT44(-21.144,17.15) AT45(-21.855,17.15) AT47(-22.566,17.15) AT48(-23.277,17.15) AT50(-23.951,17.15) AU16(-7.479,17.721) AU18(-8.452,17.721) AU20(-9.402,17.721) AU22(-10.375,17.721) AU24(-11.366,17.721) AU26(-12.339,17.721) AU28(-13.289,17.721) AU30(-14.262,17.721) AU32(-15.253,17.721) AU34(-16.226,17.721) AU36(-17.176,17.721) AU38(-18.15,17.721) AV4(-1.677,18.14) AV6(-2.351,18.14) AV7(-3.062,18.14) AV9(-3.773,18.14) AV10(-4.484,18.14) AV12(-5.196,18.14) AV13(-5.907,18.14) AV14(-6.488,18.26) AV16(-7.479,18.433) AV18(-8.452,18.433) AV19(-8.927,18.077) AV20(-9.402,18.433) AV22(-10.375,18.433) AV24(-11.366,18.433) AV26(-12.339,18.433) AV27(-12.814,18.077) AV28(-13.289,18.433) AV30(-14.262,18.433) AV32(-15.253,18.433) AV34(-16.226,18.433) AV35(-16.701,18.077) AV36(-17.176,18.433) AV38(-18.15,18.433) AV40(-19.14,18.26) AV41(-19.721,18.14) AV42(-20.433,18.14) AV44(-21.144,18.14) AV45(-21.855,18.14) AV47(-22.566,18.14) AV48(-23.277,18.14) AV50(-23.951,18.14) AW13(-6.063,18.729) AW19(-8.927,18.788) AW27(-12.814,18.788) AW35(-16.701,18.788) AW41(-19.565,18.729) AY4(-1.677,19.131) AY6(-2.351,19.131) AY7(-3.062,19.131) AY9(-3.773,19.131) AY10(-4.484,19.131) AY12(-5.497,19.154) AY14(-6.488,19.144) AY16(-7.479,19.144) AY18(-8.452,19.144) AY20(-9.402,19.144) AY22(-10.375,19.144) AY24(-11.366,19.144) AY26(-12.339,19.144) AY28(-13.289,19.144) AY30(-14.262,19.144) AY32(-15.253,19.144) AY34(-16.226,19.144) AY36(-17.176,19.144) AY38(-18.15,19.144) AY40(-19.14,19.144) AY42(-20.131,19.154) AY44(-21.144,19.131) AY45(-21.855,19.131) AY47(-22.566,19.131) AY48(-23.277,19.131) AY50(-23.951,19.131) B7(-2.962,0.584) B47(-22.666,0.584) BA12(-5.497,19.855) BA14(-6.488,19.855) BA16(-7.479,19.855) BA18(-8.452,19.855) BA19(-8.927,19.499) BA20(-9.402,19.855) BA22(-10.375,19.855) BA24(-11.366,19.855) BA26(-12.339,19.855) BA27(-12.814,19.499) BA28(-13.289,19.855) BA30(-14.262,19.855) BA32(-15.253,19.855) BA34(-16.226,19.855) BA35(-16.701,19.499) BA36(-17.176,19.855) BA38(-18.15,19.855) BA40(-19.14,19.855) BA42(-20.131,19.855) BB4(-1.556,20.121) BB5(-2.267,20.121) BB7(-2.979,20.121) BB8(-3.69,20.121) BB10(-4.507,19.984) BB19(-8.927,20.211) BB27(-12.814,20.211) BB35(-16.701,20.211) BB44(-21.121,19.984) BB46(-21.938,20.121) BB47(-22.649,20.121) BB49(-23.361,20.121) BB50(-24.072,20.121) BC10(-4.507,20.578) BC12(-5.497,20.566) BC14(-6.488,20.566) BC16(-7.479,20.566) BC18(-8.452,20.566) BC20(-9.402,20.566) BC22(-10.375,20.566) BC24(-11.366,20.566) BC26(-12.339,20.566) BC28(-13.289,20.566) BC30(-14.262,20.566) BC32(-15.253,20.566) BC34(-16.226,20.566) BC36(-17.176,20.566) BC38(-18.15,20.566) BC40(-19.14,20.566) BC42(-20.131,20.566) BC44(-21.121,20.578) BD5(-2.249,21.116) BD7(-3.102,21.116) BD10(-4.507,21.271) BD12(-5.497,21.277) BD14(-6.488,21.277) BD16(-7.479,21.277) BD18(-8.452,21.277) BD19(-8.927,20.922) BD20(-9.402,21.277) BD22(-10.375,21.277) BD24(-11.366,21.277) BD26(-12.289,21.218) BD27(-12.814,20.922) BD28(-13.339,21.218) BD30(-14.262,21.277) BD32(-15.253,21.277) BD34(-16.226,21.277) BD35(-16.701,20.922) BD36(-17.176,21.277) BD38(-18.15,21.277) BD40(-19.14,21.277) BD42(-20.131,21.277) BD44(-21.121,21.271) BD47(-22.526,21.116) BD49(-23.379,21.116) BE3(-1.171,21.394) BE8(-3.494,21.561) BE19(-8.927,21.633) BE35(-16.701,21.633) BE46(-22.134,21.561) BE51(-24.457,21.394) BF4(-1.651,21.977) BF6(-2.701,22.053) BF10(-4.507,21.982) BF12(-5.497,21.951) BF14(-6.488,21.951) BF16(-7.479,21.951) BF18(-8.426,21.951) BF20(-9.428,21.951) BF22(-10.375,21.951) BF24(-11.366,21.951) BF26(-12.351,21.809) BF28(-13.277,21.809) BF30(-14.262,21.951) BF32(-15.253,21.951) BF34(-16.2,21.951) BF36(-17.202,21.951) BF38(-18.15,21.951) BF40(-19.14,21.951) BF42(-20.131,21.951) BF44(-21.121,21.982) BF48(-22.927,22.053) BF50(-23.977,21.977) BG5(-2.234,22.457) BG7(-3.261,22.523) BG47(-22.367,22.523) BG49(-23.394,22.457) BH7(-2.962,23.044) BH47(-22.666,23.044) C5(-2.234,1.171) C7(-3.261,1.105) C47(-22.367,1.105) C49(-23.394,1.171) D4(-1.651,1.651) D6(-2.701,1.576) D10(-4.507,1.646) D12(-5.497,1.677) D14(-6.488,1.677) D16(-7.479,1.677) D18(-8.426,1.677) D20(-9.428,1.677) D22(-10.375,1.677) D24(-11.366,1.677) D26(-12.351,1.819) D28(-13.277,1.819) D30(-14.262,1.677) D32(-15.253,1.677) D34(-16.2,1.677) D36(-17.202,1.677) D38(-18.15,1.677) D40(-19.14,1.677) D42(-20.131,1.677) D44(-21.121,1.646) D48(-22.927,1.576) D50(-23.977,1.651) E3(-1.171,2.234) E8(-3.494,2.067) E19(-8.927,1.995) E35(-16.701,1.995) E46(-22.134,2.067) E51(-24.457,2.234) F5(-2.249,2.512) F7(-3.102,2.512) F10(-4.507,2.357) F12(-5.497,2.351) F14(-6.488,2.351) F16(-7.479,2.351) F18(-8.452,2.351) F19(-8.927,2.706) F20(-9.402,2.351) F22(-10.375,2.351) F24(-11.366,2.351) F26(-12.289,2.41) F27(-12.814,2.706) F28(-13.339,2.41) F30(-14.262,2.351) F32(-15.253,2.351) F34(-16.226,2.351) F35(-16.701,2.706) F36(-17.176,2.351) F38(-18.15,2.351) F40(-19.14,2.351) F42(-20.131,2.351) F44(-21.121,2.357) F47(-22.526,2.512) F49(-23.379,2.512) G10(-4.507,3.05) G12(-5.497,3.062) G14(-6.488,3.062) G16(-7.479,3.062) G18(-8.452,3.062) G20(-9.402,3.062) G22(-10.375,3.062) G24(-11.366,3.062) G26(-12.339,3.062) G28(-13.289,3.062) G30(-14.262,3.062) G32(-15.253,3.062) G34(-16.226,3.062) G36(-17.176,3.062) G38(-18.15,3.062) G40(-19.14,3.062) G42(-20.131,3.062) G44(-21.121,3.05) H4(-1.556,3.507) H5(-2.267,3.507) H7(-2.979,3.507) H8(-3.69,3.507) H10(-4.507,3.644) H19(-8.927,3.418) H27(-12.814,3.418) H35(-16.701,3.418) H44(-21.121,3.644) H46(-21.938,3.507) H47(-22.649,3.507) H49(-23.361,3.507) H50(-24.072,3.507) J12(-5.497,3.773) J14(-6.488,3.773) J16(-7.479,3.773) J18(-8.452,3.773) J19(-8.927,4.129) J20(-9.402,3.773) J22(-10.375,3.773) J24(-11.366,3.773) J26(-12.339,3.773) J27(-12.814,4.129) J28(-13.289,3.773) J30(-14.262,3.773) J32(-15.253,3.773) J34(-16.226,3.773) J35(-16.701,4.129) J36(-17.176,3.773) J38(-18.15,3.773) J40(-19.14,3.773) J42(-20.131,3.773) K4(-1.677,4.497) K6(-2.351,4.497) K7(-3.062,4.497) K9(-3.773,4.497) K10(-4.484,4.497) K12(-5.497,4.474) K14(-6.488,4.484) K16(-7.479,4.484) K18(-8.452,4.484) K20(-9.402,4.484) K22(-10.375,4.484) K24(-11.366,4.484) K26(-12.339,4.484) K28(-13.289,4.484) K30(-14.262,4.484) K32(-15.253,4.484) K34(-16.226,4.484) K36(-17.176,4.484) K38(-18.15,4.484) K40(-19.14,4.484) K42(-20.131,4.474) K44(-21.144,4.497) K45(-21.855,4.497) K47(-22.566,4.497) K48(-23.277,4.497) K50(-23.951,4.497) L13(-6.063,4.899) L19(-8.927,4.84) L27(-12.814,4.84) L35(-16.701,4.84) L41(-19.565,4.899) M4(-1.677,5.488) M6(-2.351,5.488) M7(-3.062,5.488) M9(-3.773,5.488) M10(-4.484,5.488) M12(-5.196,5.488) M13(-5.907,5.488) M14(-6.488,5.368) M16(-7.479,5.196) M18(-8.452,5.196) M19(-8.927,5.551) M20(-9.402,5.196) M22(-10.375,5.196) M24(-11.366,5.196) M26(-12.339,5.196) M27(-12.814,5.551) M28(-13.289,5.196) M30(-14.262,5.196) M32(-15.253,5.196) M34(-16.226,5.196) M35(-16.701,5.551) M36(-17.176,5.196) M38(-18.15,5.196) M40(-19.14,5.368) M41(-19.721,5.488) M42(-20.433,5.488) M44(-21.144,5.488) M45(-21.855,5.488) M47(-22.566,5.488) M48(-23.277,5.488) M50(-23.951,5.488) N16(-7.479,5.907) N18(-8.452,5.907) N20(-9.402,5.907) N22(-10.375,5.907) N24(-11.366,5.907) N26(-12.339,5.907) N28(-13.289,5.907) N30(-14.262,5.907) N32(-15.253,5.907) N34(-16.226,5.907) N36(-17.176,5.907) N38(-18.15,5.907) P4(-1.677,6.479) P6(-2.351,6.479) P7(-3.062,6.479) P9(-3.773,6.479) P10(-4.484,6.479) P12(-5.196,6.479) P13(-5.907,6.479) P14(-6.509,6.479) P16(-7.479,6.618) P18(-8.452,6.618) P19(-8.927,6.262) P20(-9.402,6.618) P22(-10.375,6.618) P24(-11.366,6.618) P26(-12.339,6.618) P27(-12.814,6.262) P28(-13.289,6.618) P30(-14.262,6.618) P32(-15.253,6.618) P34(-16.226,6.618) P35(-16.701,6.262) P36(-17.176,6.618) P38(-18.15,6.618) P40(-19.119,6.479) P41(-19.721,6.479) P42(-20.433,6.479) P44(-21.144,6.479) P45(-21.855,6.479) P47(-22.566,6.479) P48(-23.277,6.479) P50(-23.951,6.479) T4(-1.677,7.426) T6(-2.351,7.452) T7(-3.062,7.452) T9(-3.773,7.452) T10(-4.484,7.452) T12(-5.196,7.452) T13(-5.907,7.452) T14(-6.618,7.452) T40(-19.01,7.452) T41(-19.721,7.452) T42(-20.433,7.452) T44(-21.144,7.452) T45(-21.855,7.452) T47(-22.566,7.452) T48(-23.277,7.452) T50(-23.951,7.426) U5(-1.995,7.927) U6(-2.706,7.927) U8(-3.418,7.927) U9(-4.129,7.927) U11(-4.84,7.927) U12(-5.551,7.927) U14(-6.262,7.927) U40(-19.366,7.927) U42(-20.077,7.927) U43(-20.788,7.927) U45(-21.499,7.927) U46(-22.211,7.927) U48(-22.922,7.927) U49(-23.633,7.927) V4(-1.677,8.428) V6(-2.351,8.402) V7(-3.062,8.402) V9(-3.773,8.402) V10(-4.484,8.402) V12(-5.196,8.402) V13(-5.907,8.402) V14(-6.618,8.402) V40(-19.01,8.402) V41(-19.721,8.402) V42(-20.433,8.402) V44(-21.144,8.402) V45(-21.855,8.402) V47(-22.566,8.402) V48(-23.277,8.402) V50(-23.951,8.428) Y4(-1.677,9.375) Y6(-2.351,9.375) Y7(-3.062,9.375) Y9(-3.773,9.375) Y10(-4.484,9.375) Y12(-5.196,9.375) Y13(-5.907,9.375) Y14(-6.618,9.375) Y40(-19.01,9.375) Y41(-19.721,9.375) Y42(-20.433,9.375) Y44(-21.144,9.375) Y45(-21.855,9.375) Y47(-22.566,9.375) Y48(-23.277,9.375) Y50(-23.951,9.375)
